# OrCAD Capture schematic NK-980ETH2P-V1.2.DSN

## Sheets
1 Block Diagram: size A; title: NK-980ETH2P; rev: 1.2; company: nuvoTon Technology Corp.; note: Block Diagram
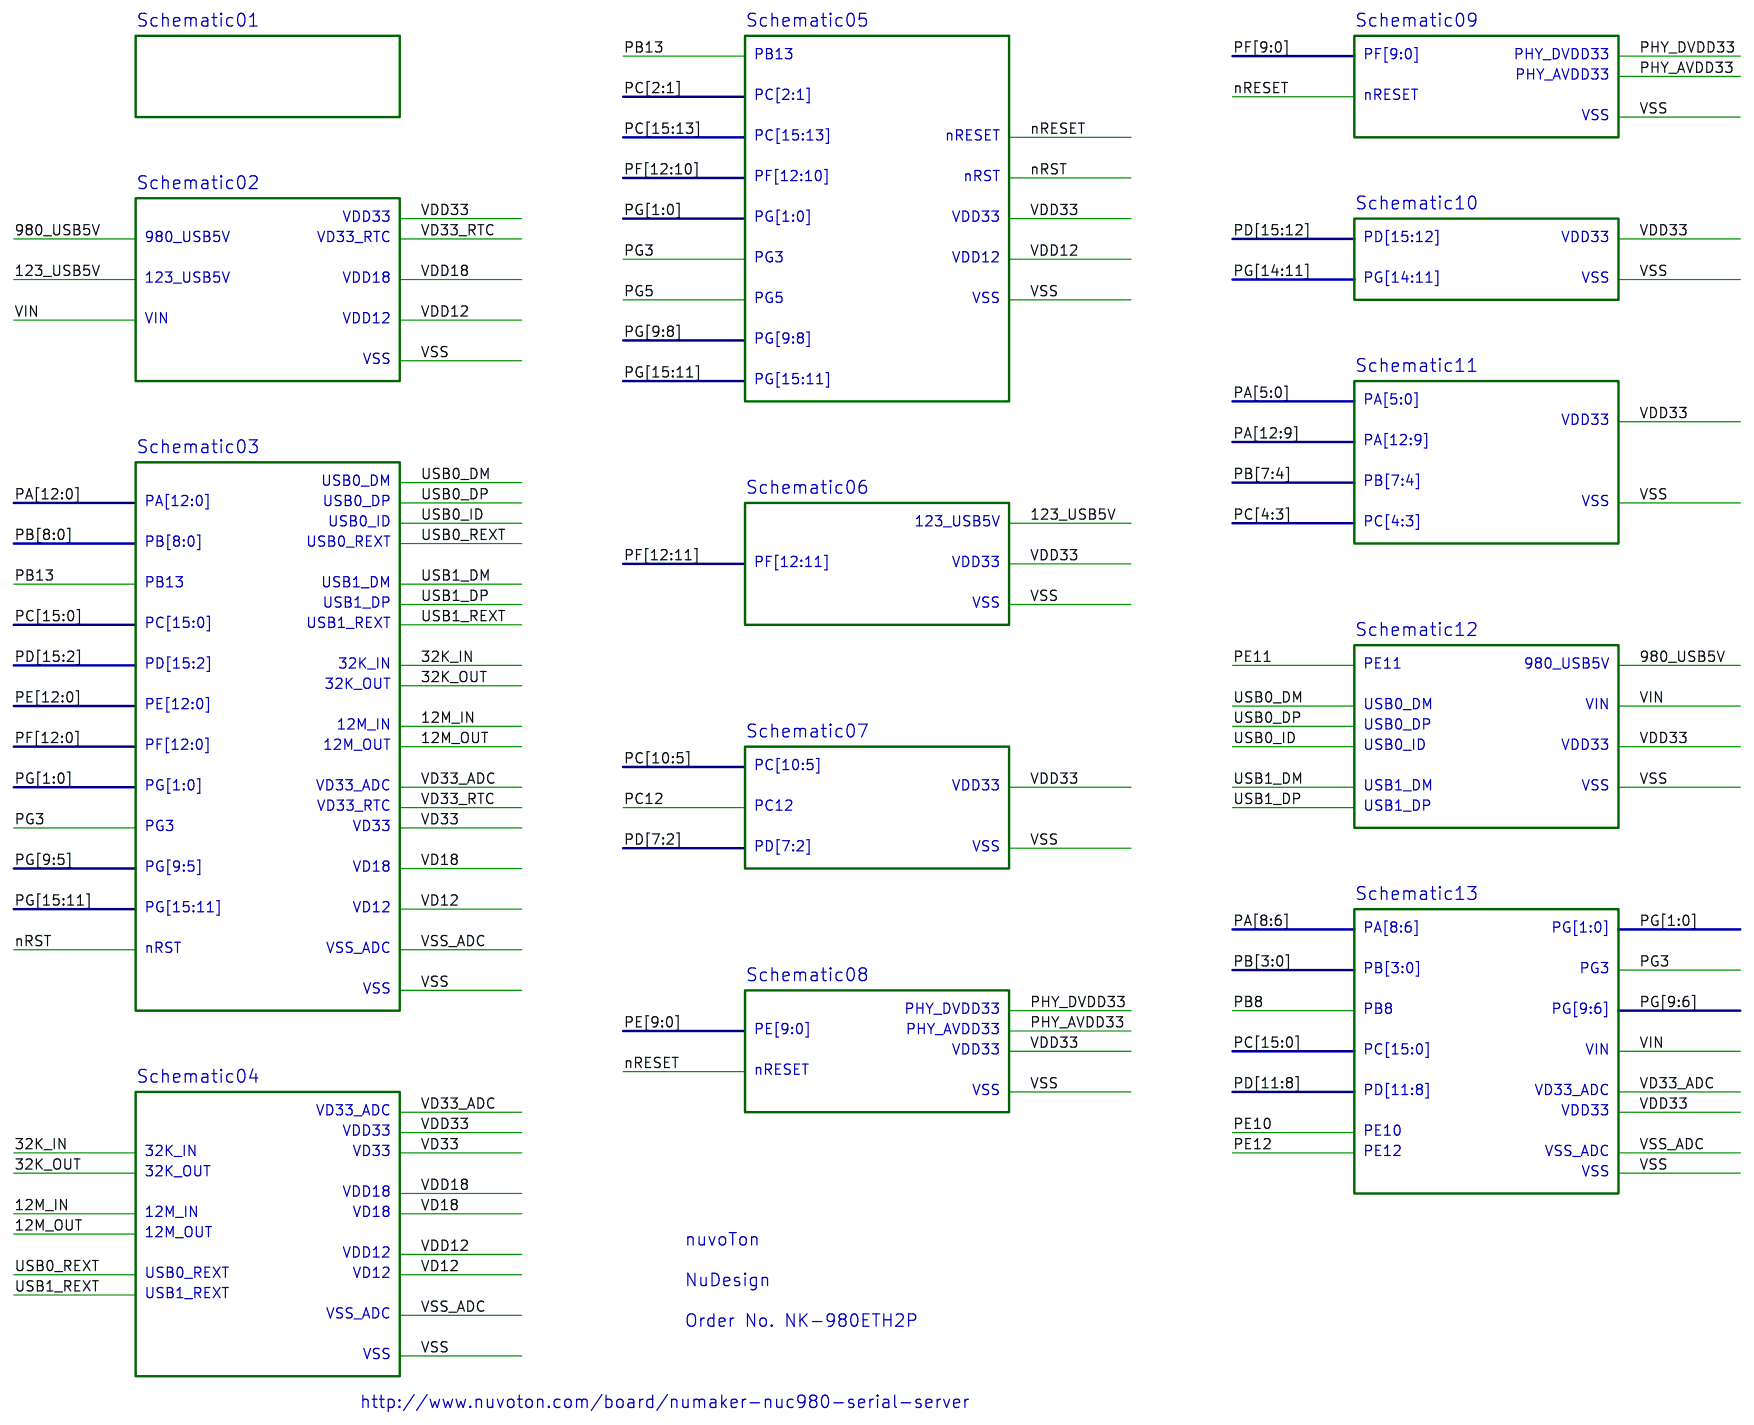
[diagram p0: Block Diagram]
2 Memory: size A; note: Memory; block Schematic07
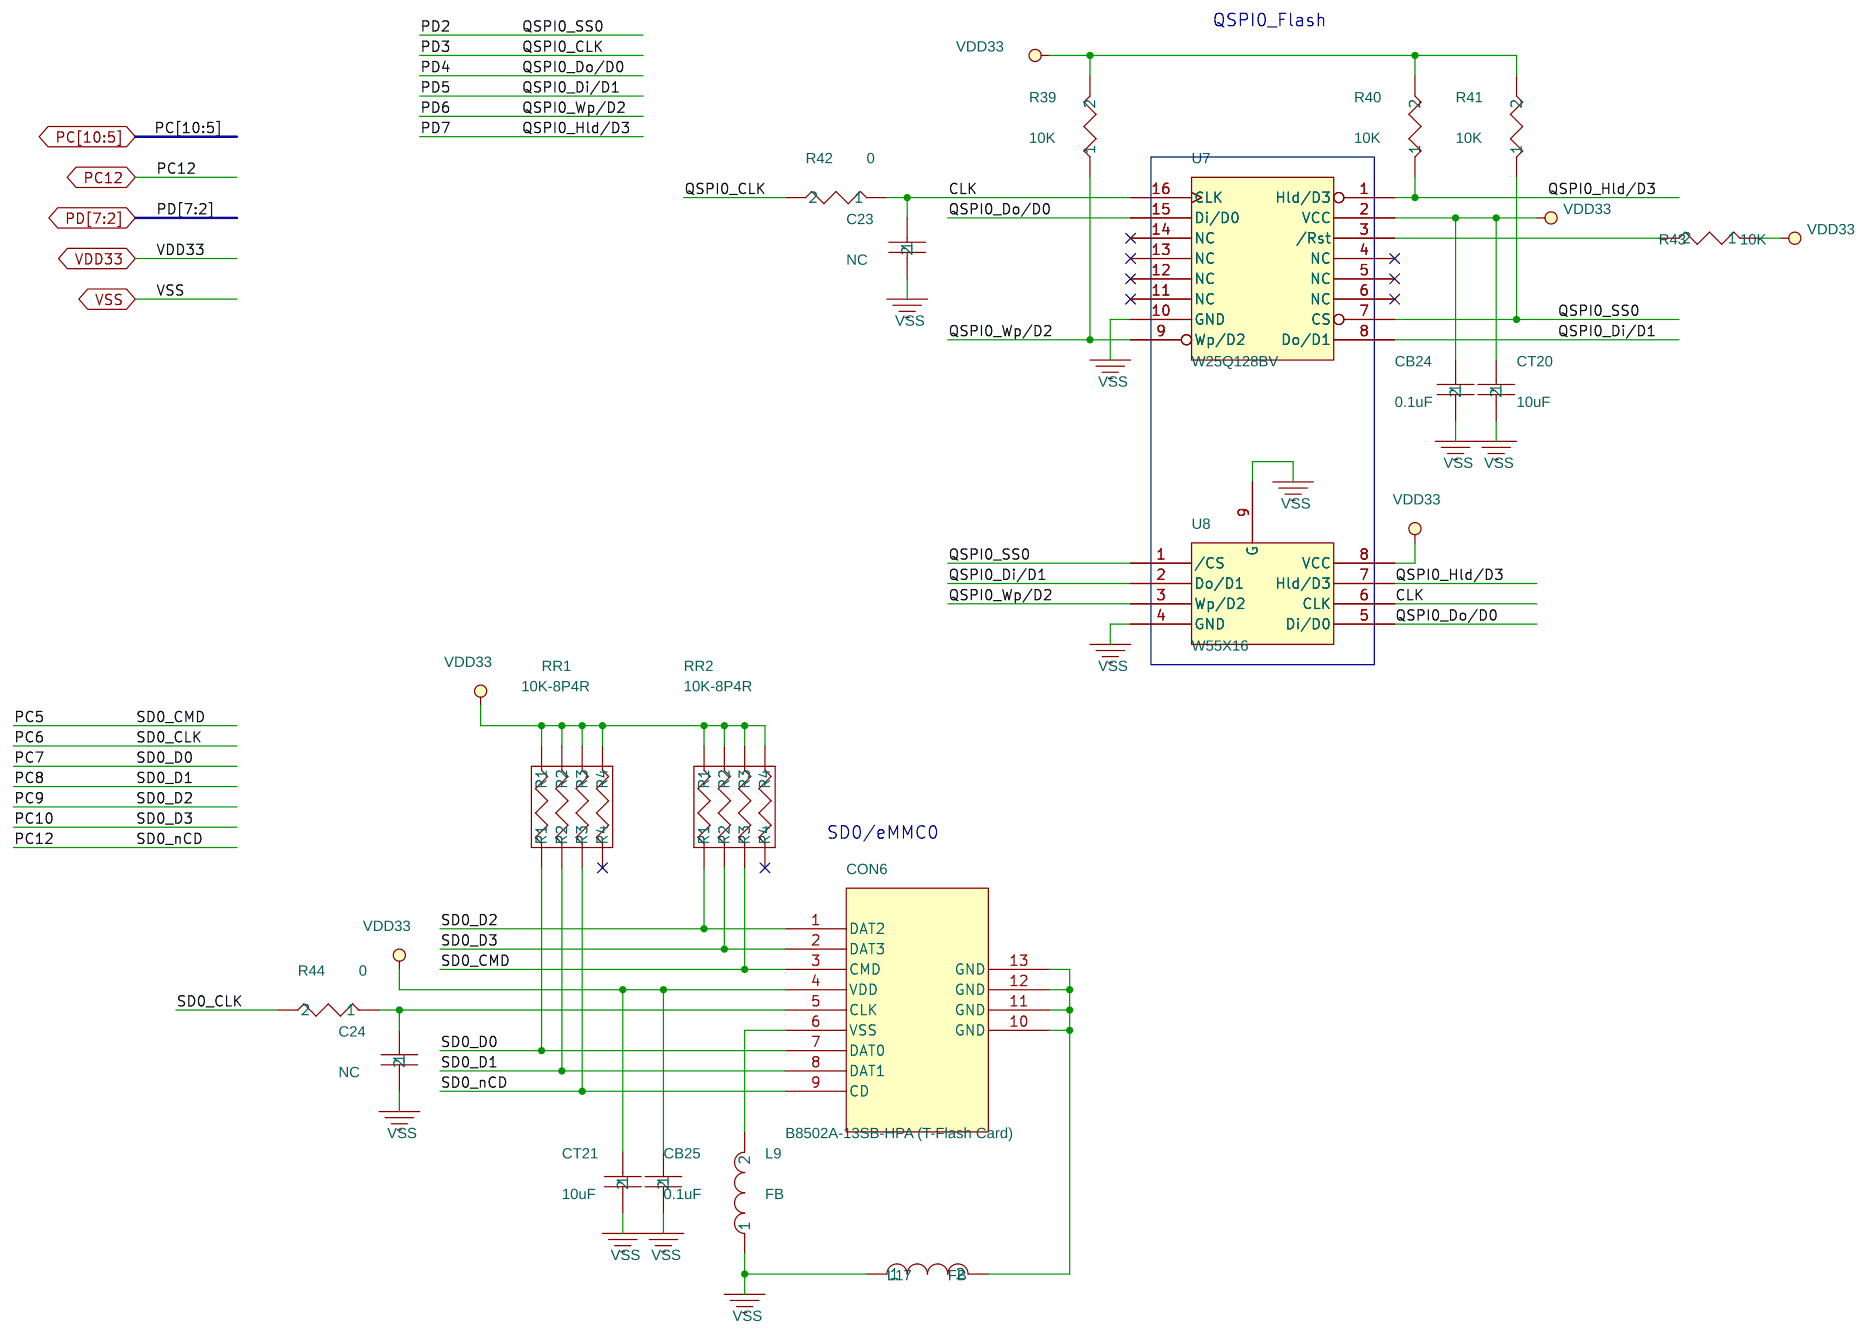
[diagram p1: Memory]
3 RMII_PE: size A; note: RMII_PE; block Schematic08
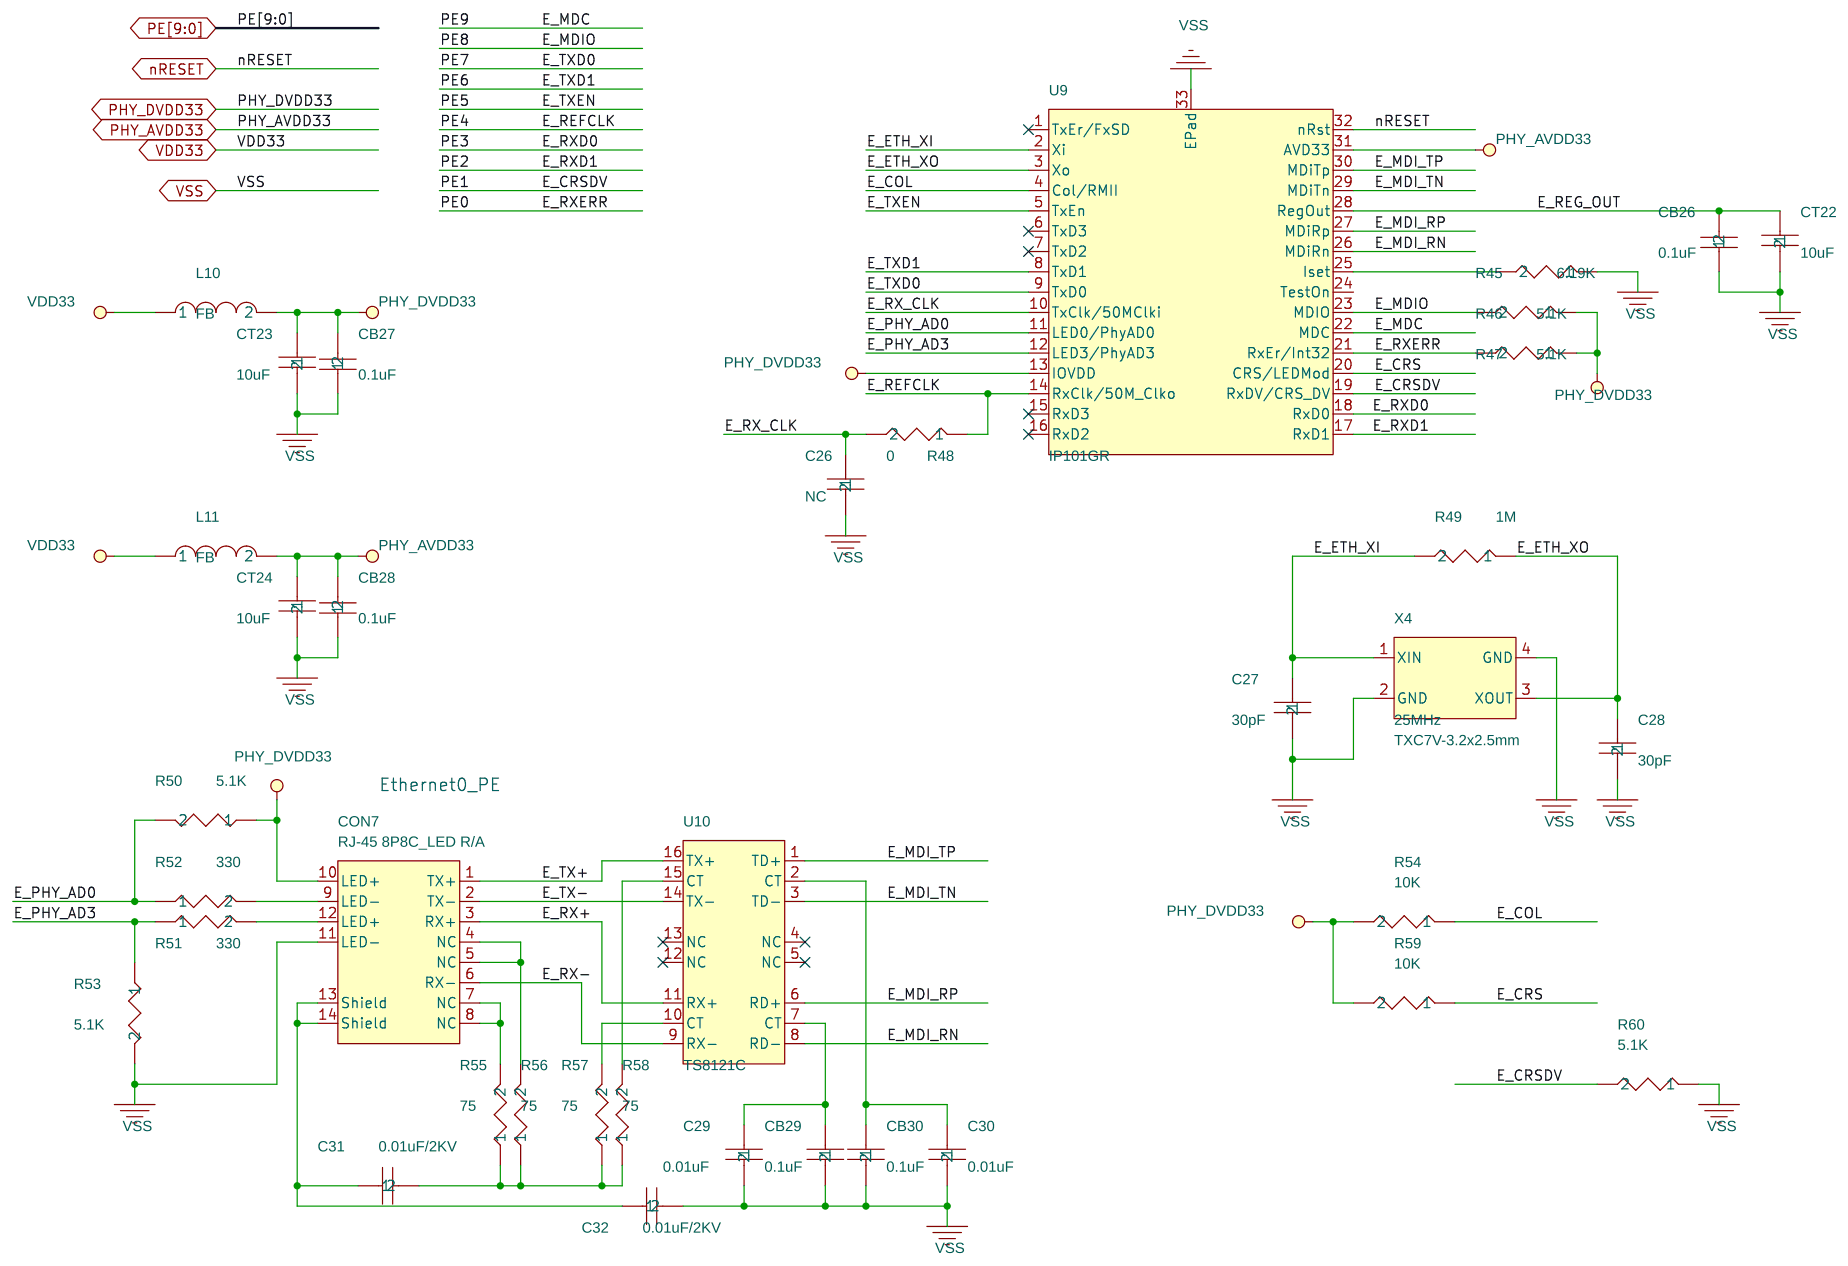
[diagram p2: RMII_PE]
4 Power Filter: size A; note: Power Filter; block Schematic04
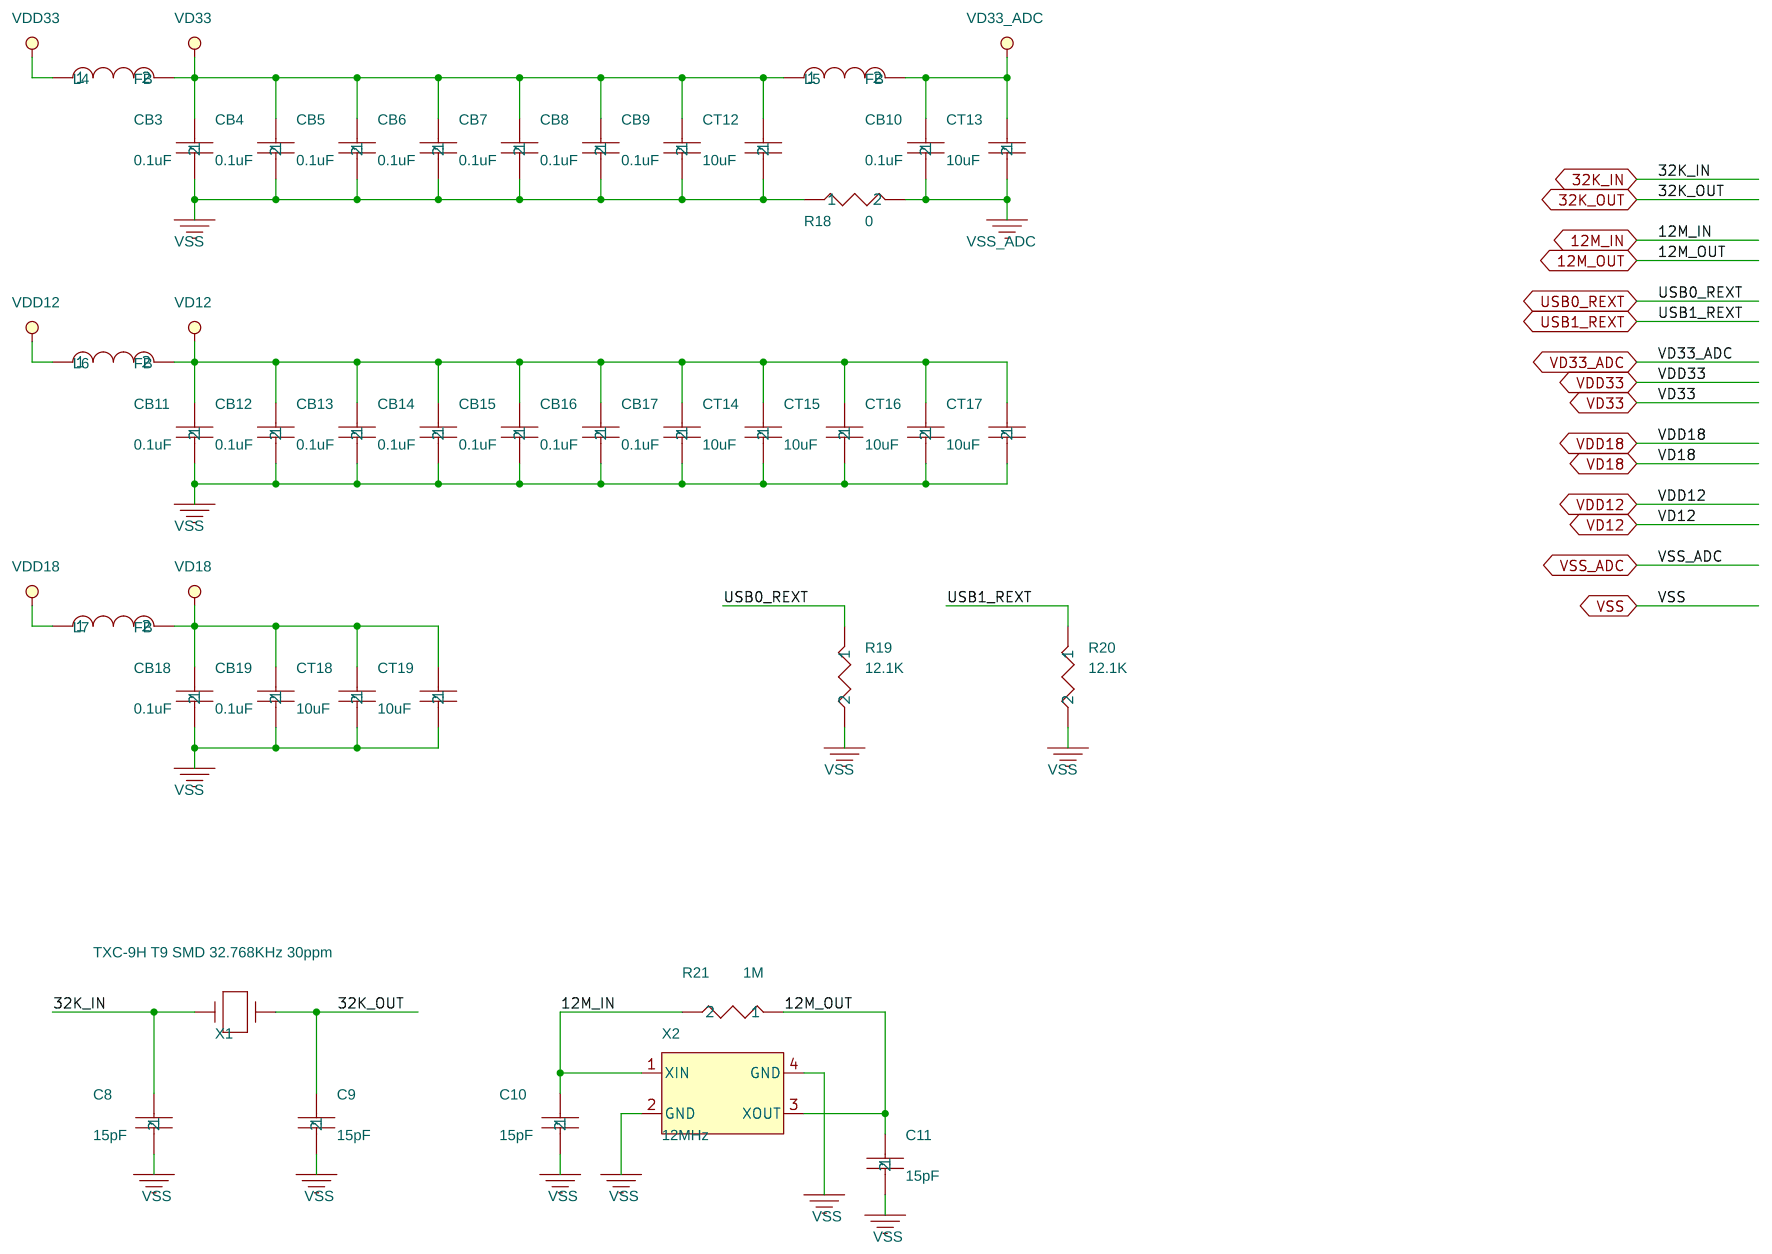
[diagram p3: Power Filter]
5 RMII_PF: size A; note: RMII_PF; block Schematic09
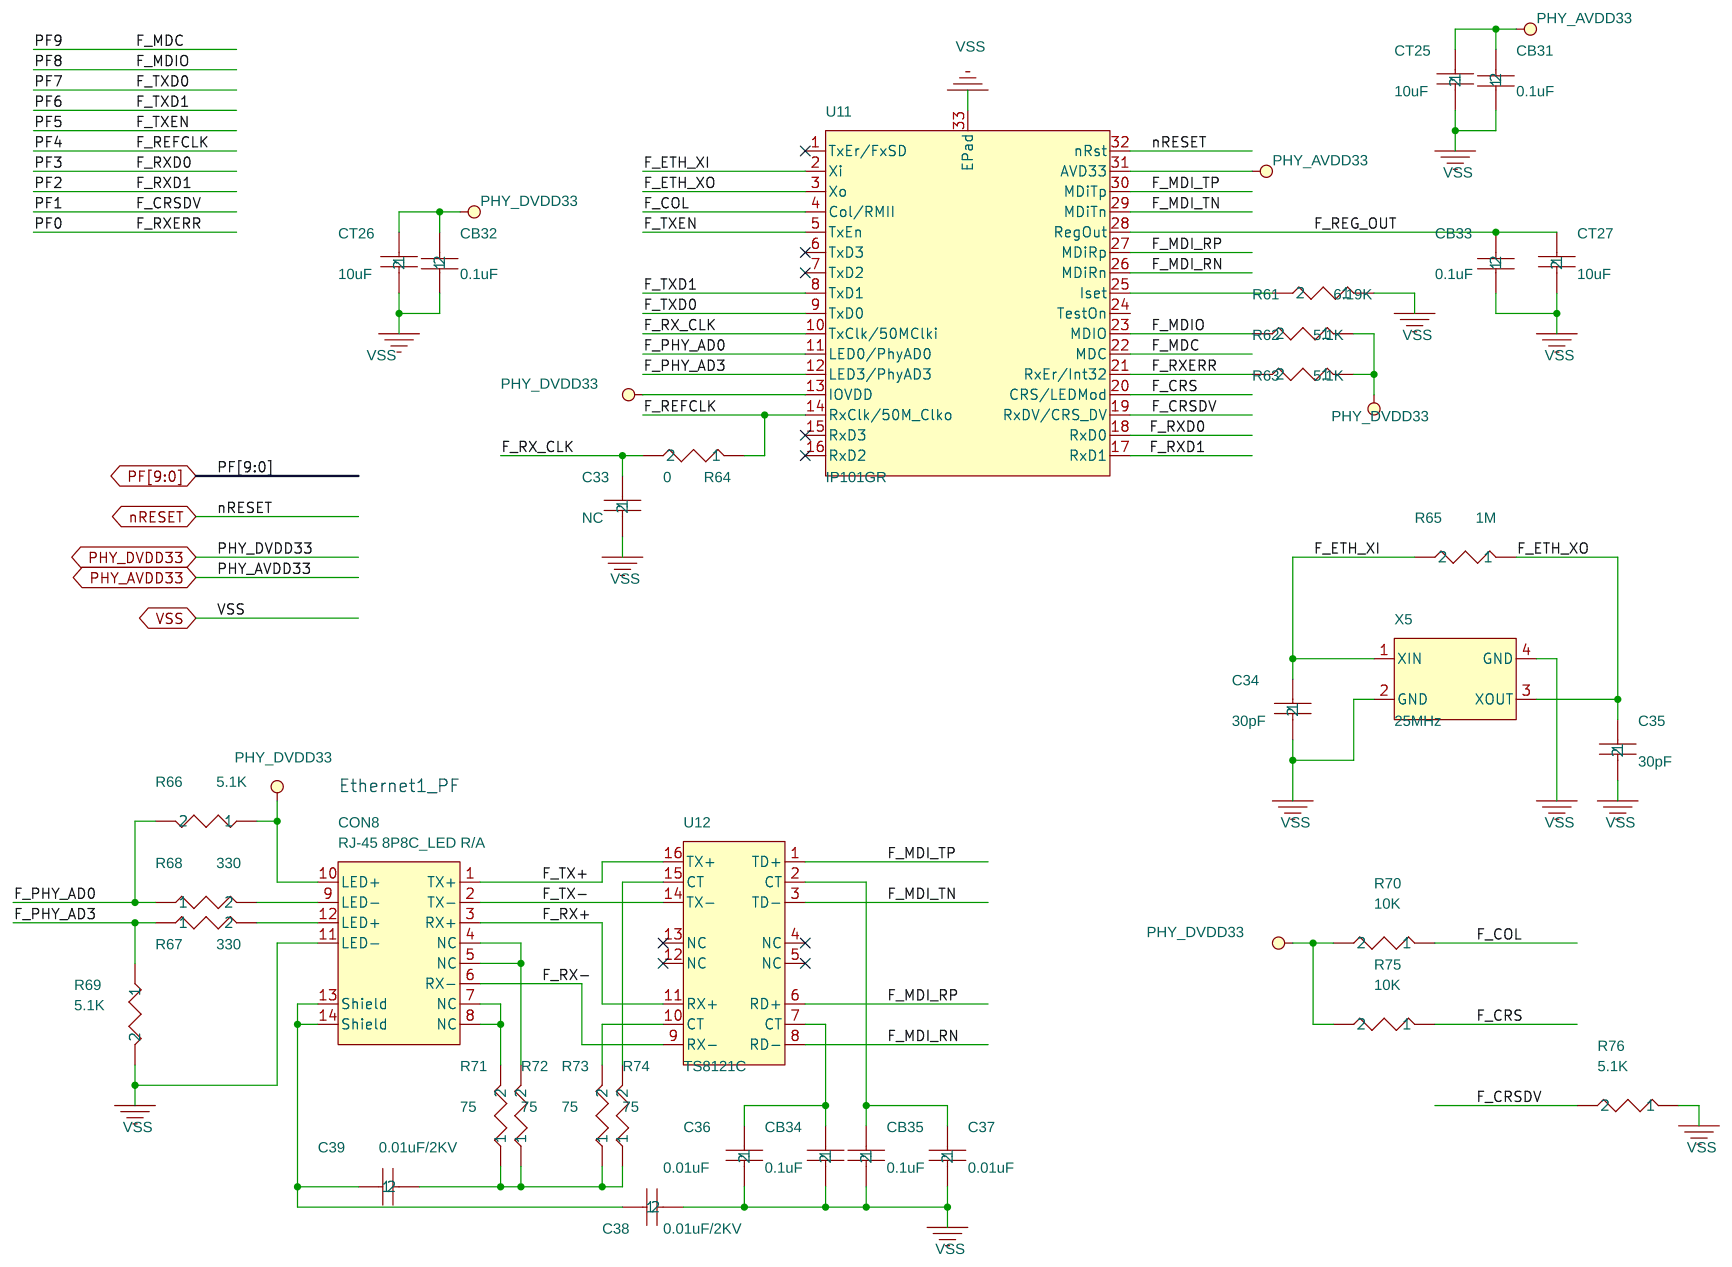
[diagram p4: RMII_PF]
6 UART_A: size A; note: UART_A; block Schematic10
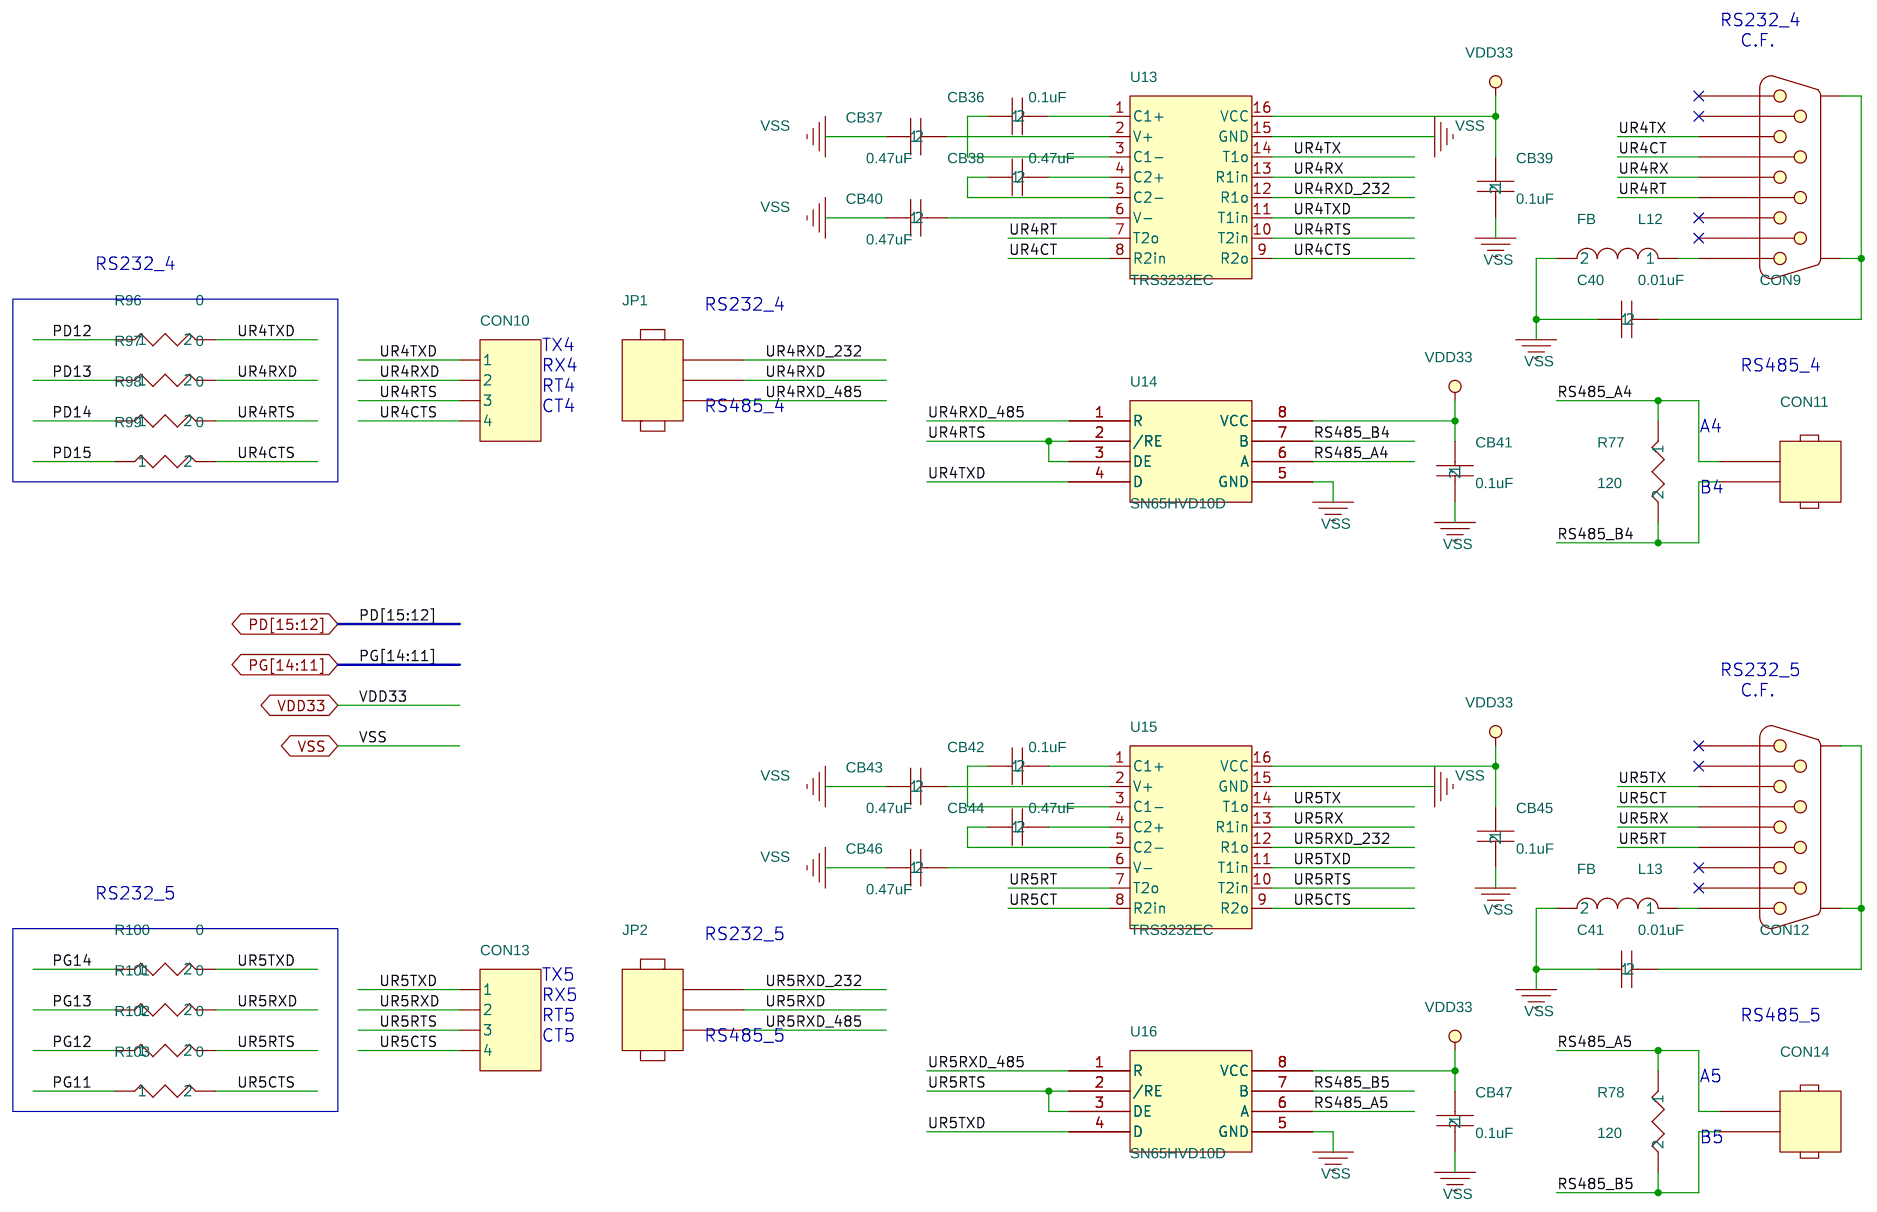
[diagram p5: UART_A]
7 GPIO List: note: GPIO List
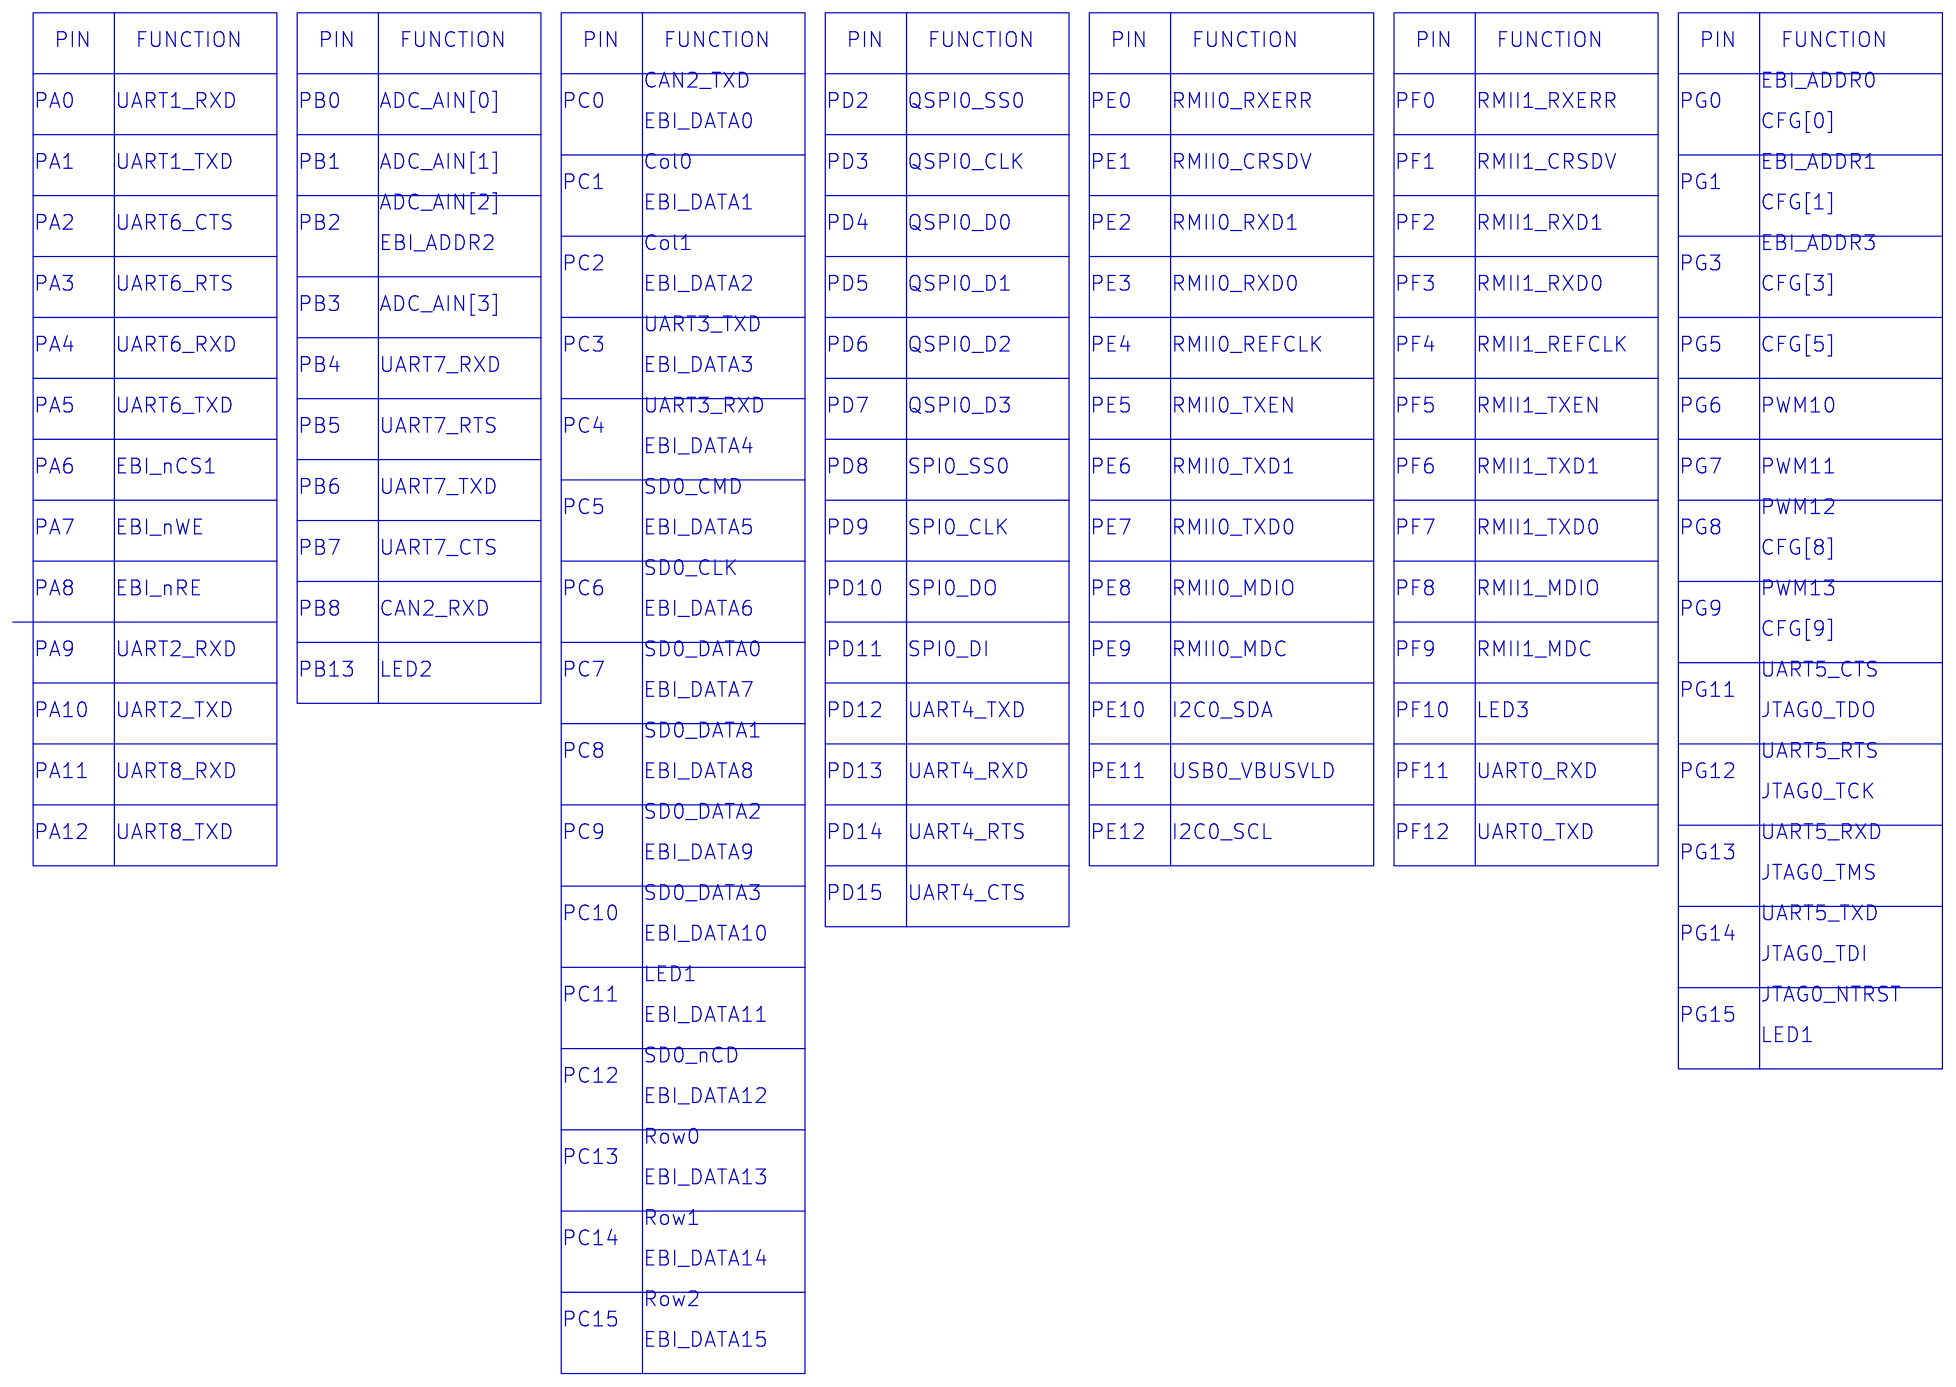
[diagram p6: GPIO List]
8 Power: size A; note: Power; block Schematic02
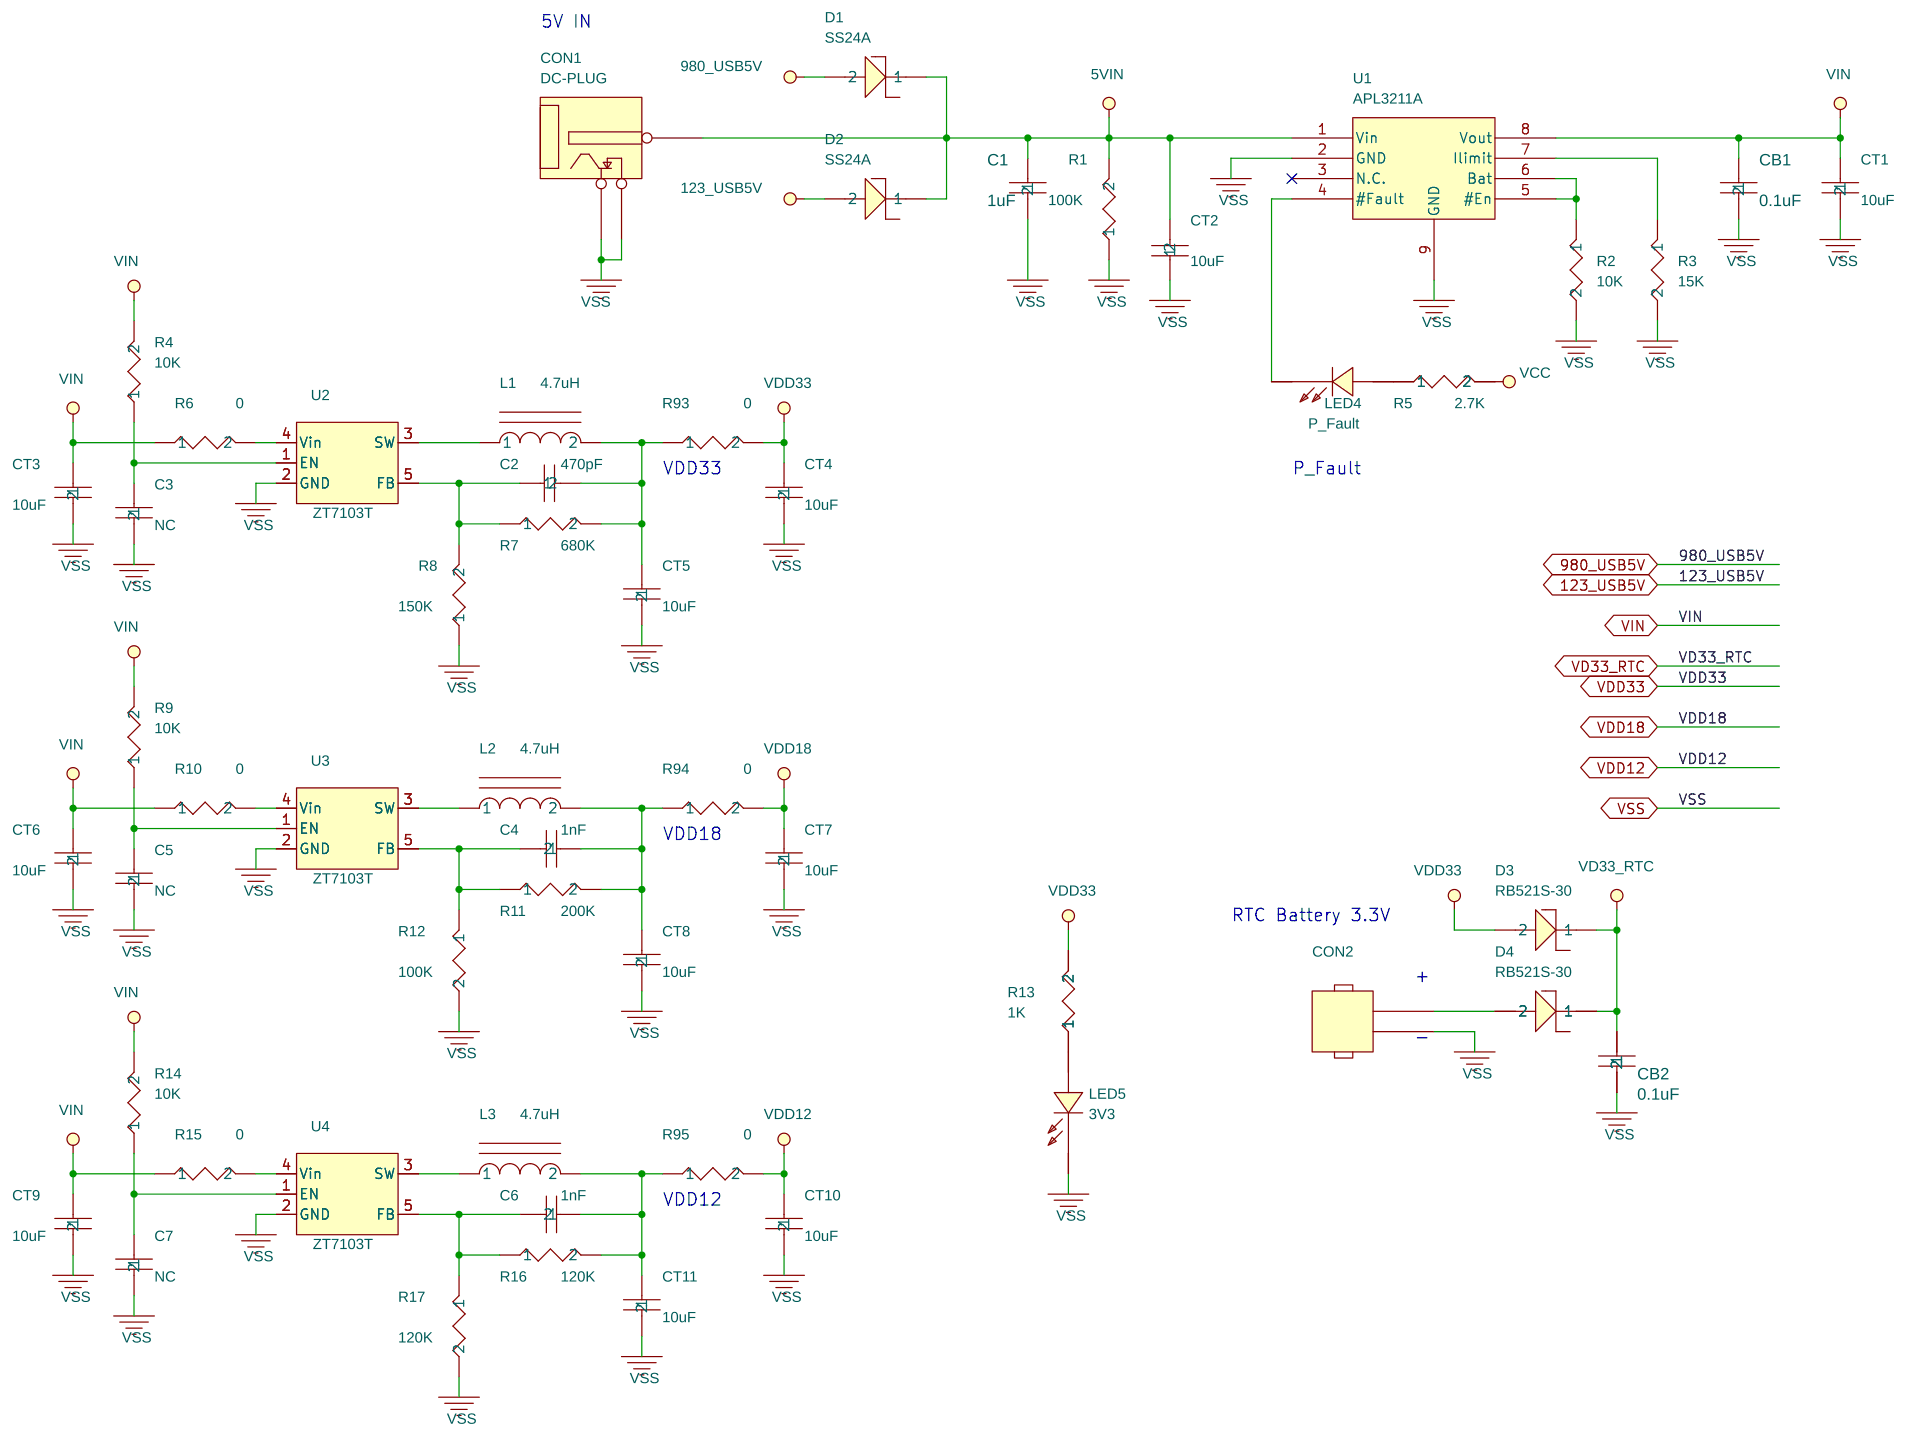
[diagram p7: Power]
9 UART_B: size A; note: UART_B; block Schematic11
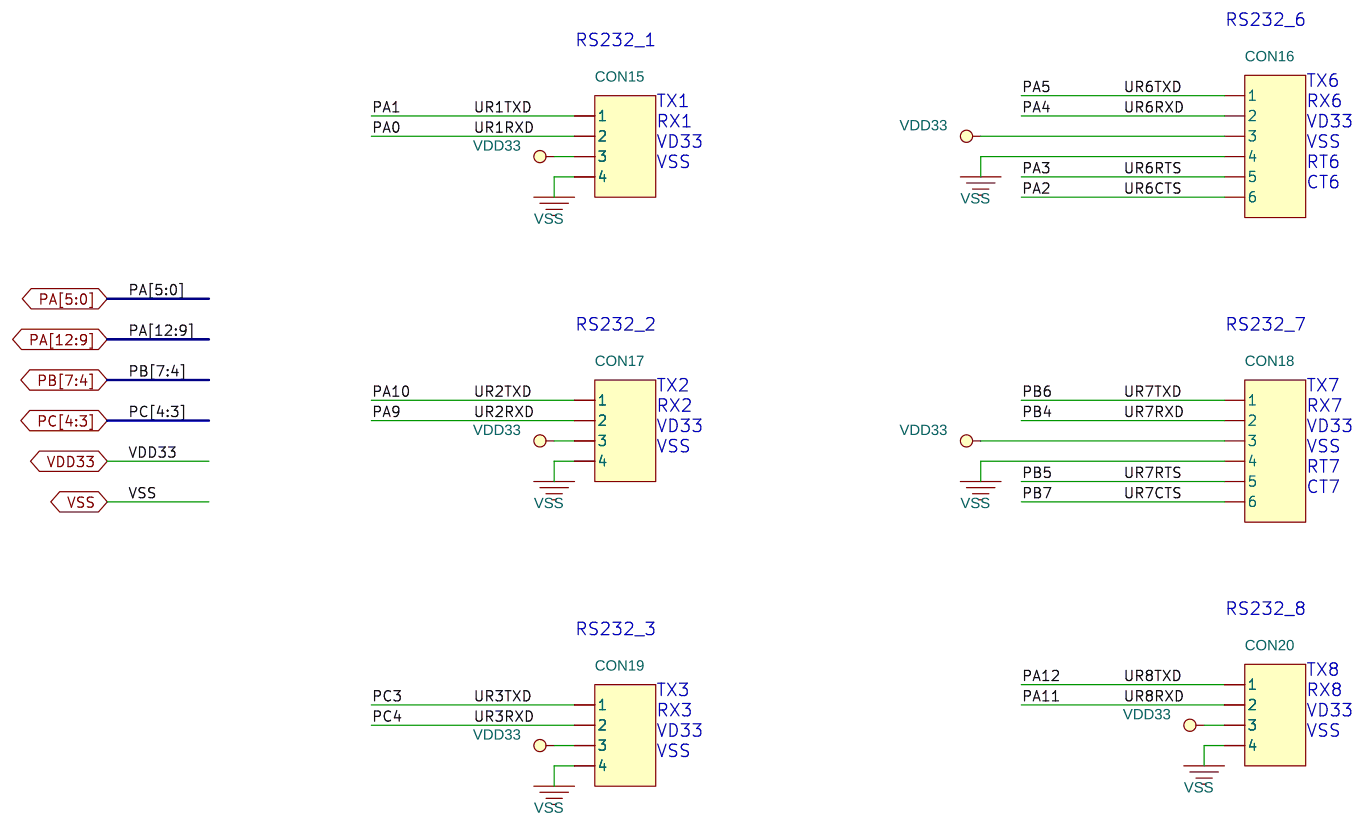
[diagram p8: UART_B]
10 Configure: size Custom; note: Configure; block Schematic05
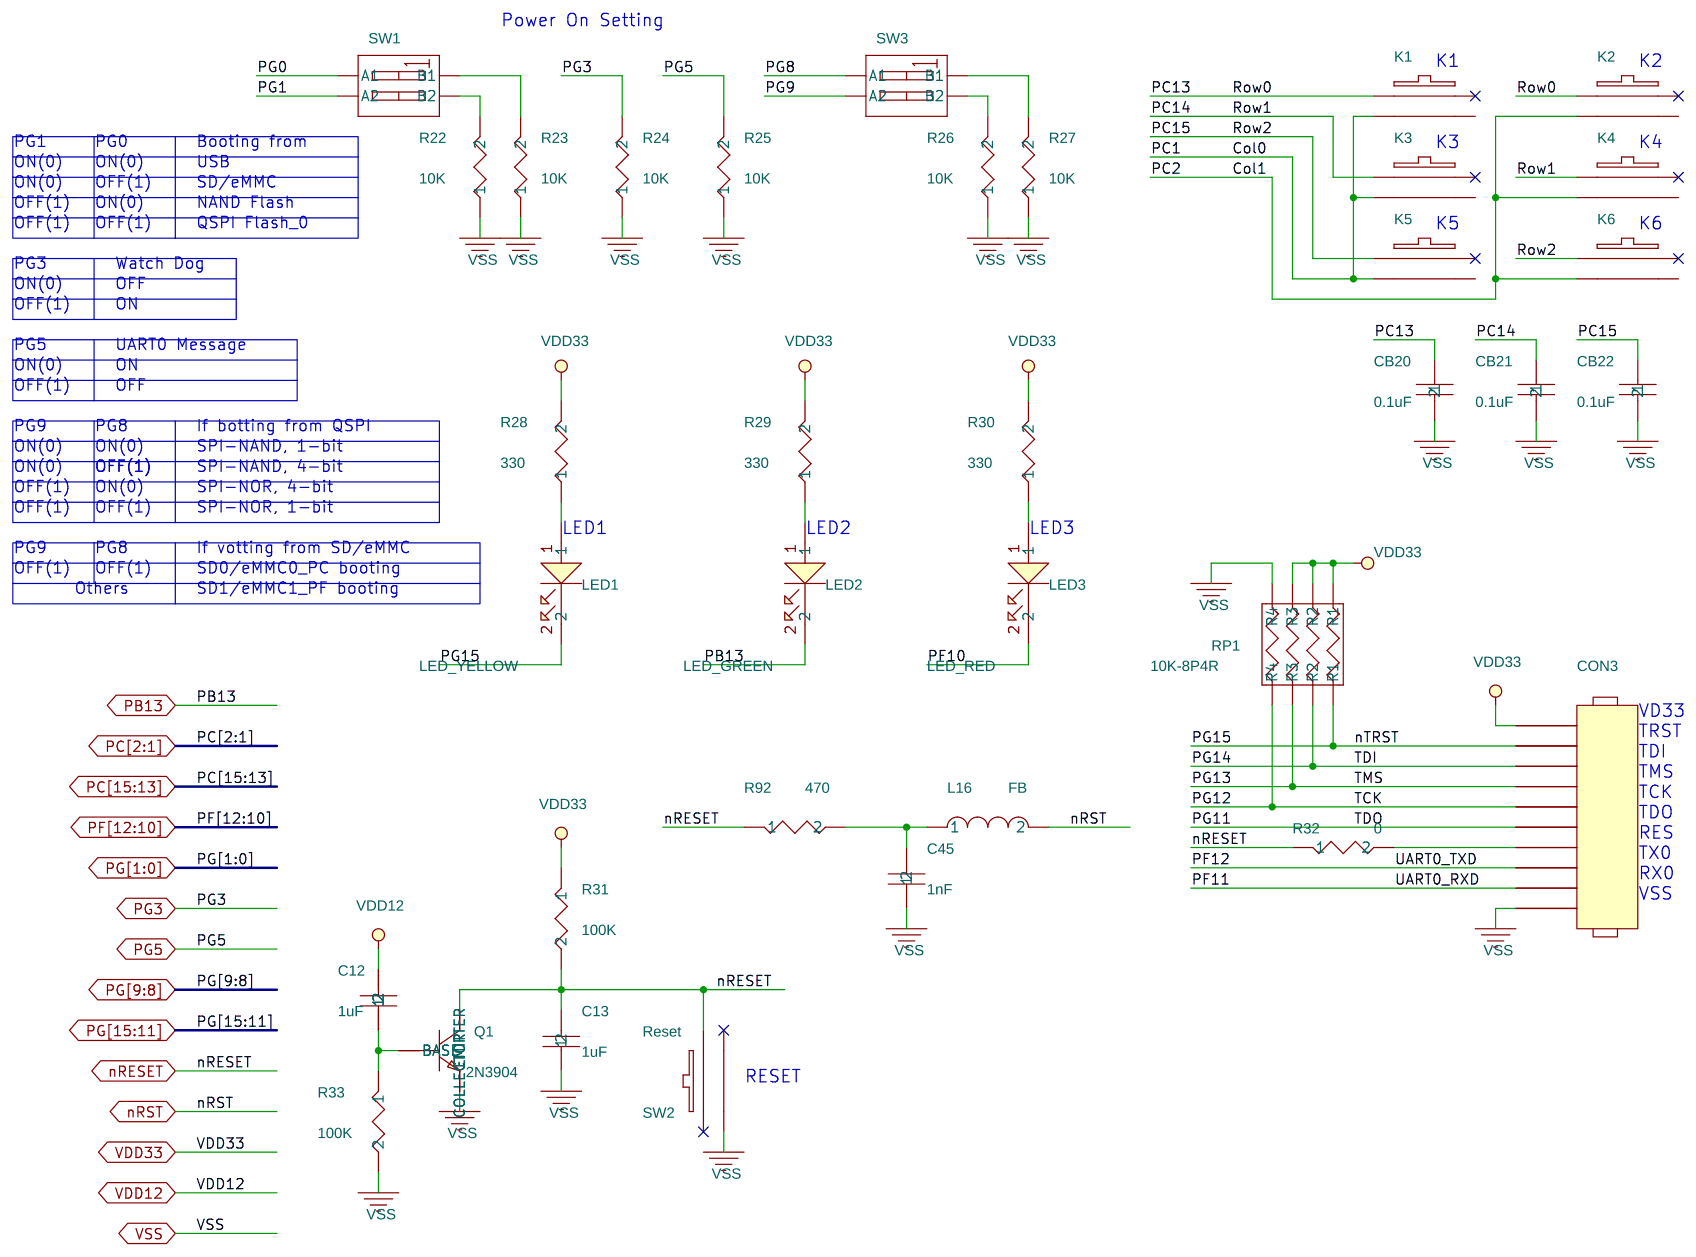
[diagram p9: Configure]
11 USB: size A; note: USB; block Schematic12
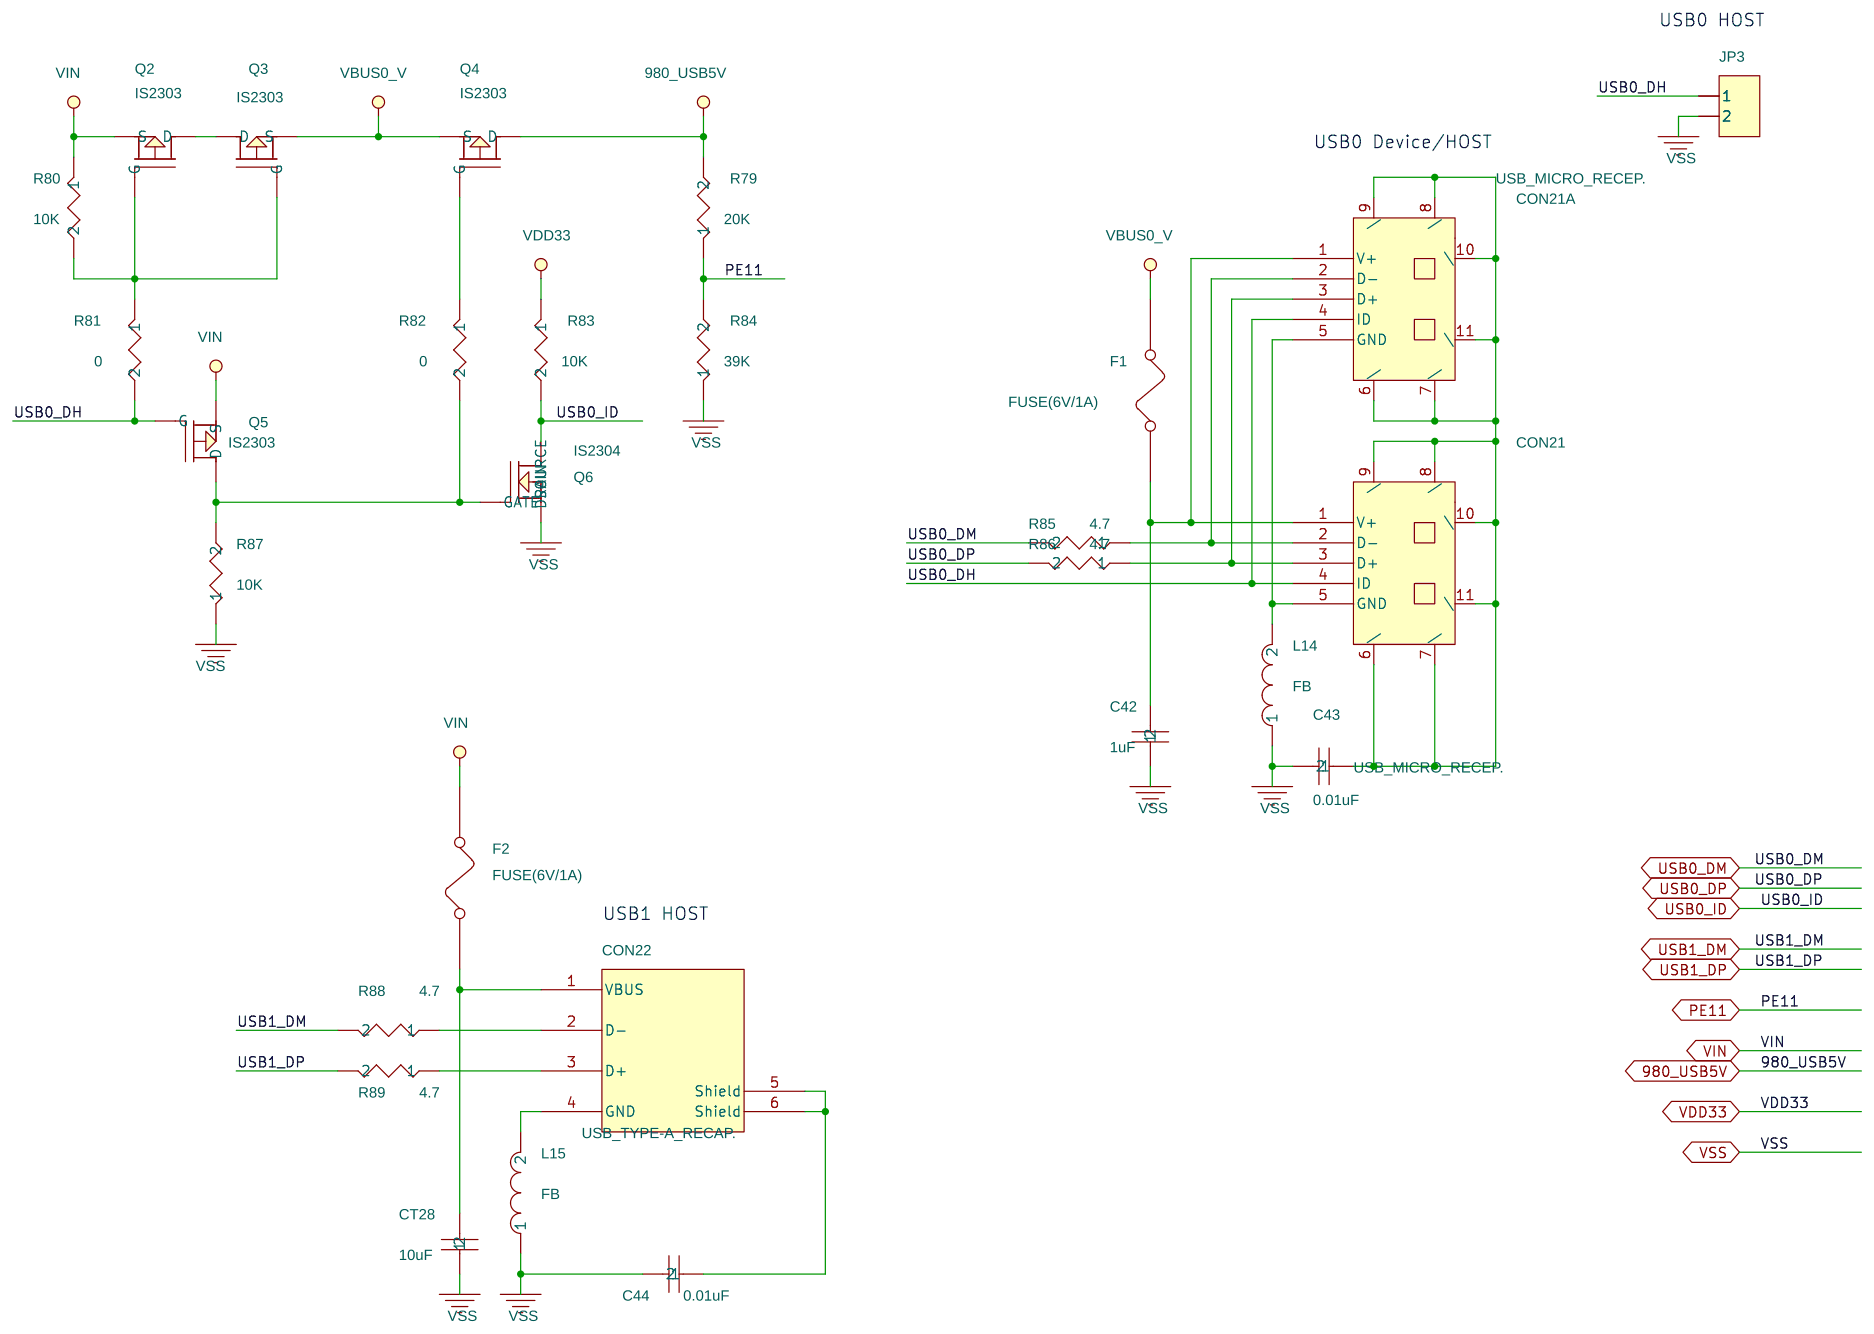
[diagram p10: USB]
12 NUC980DK: size Custom; note: NUC980DK; block Schematic03
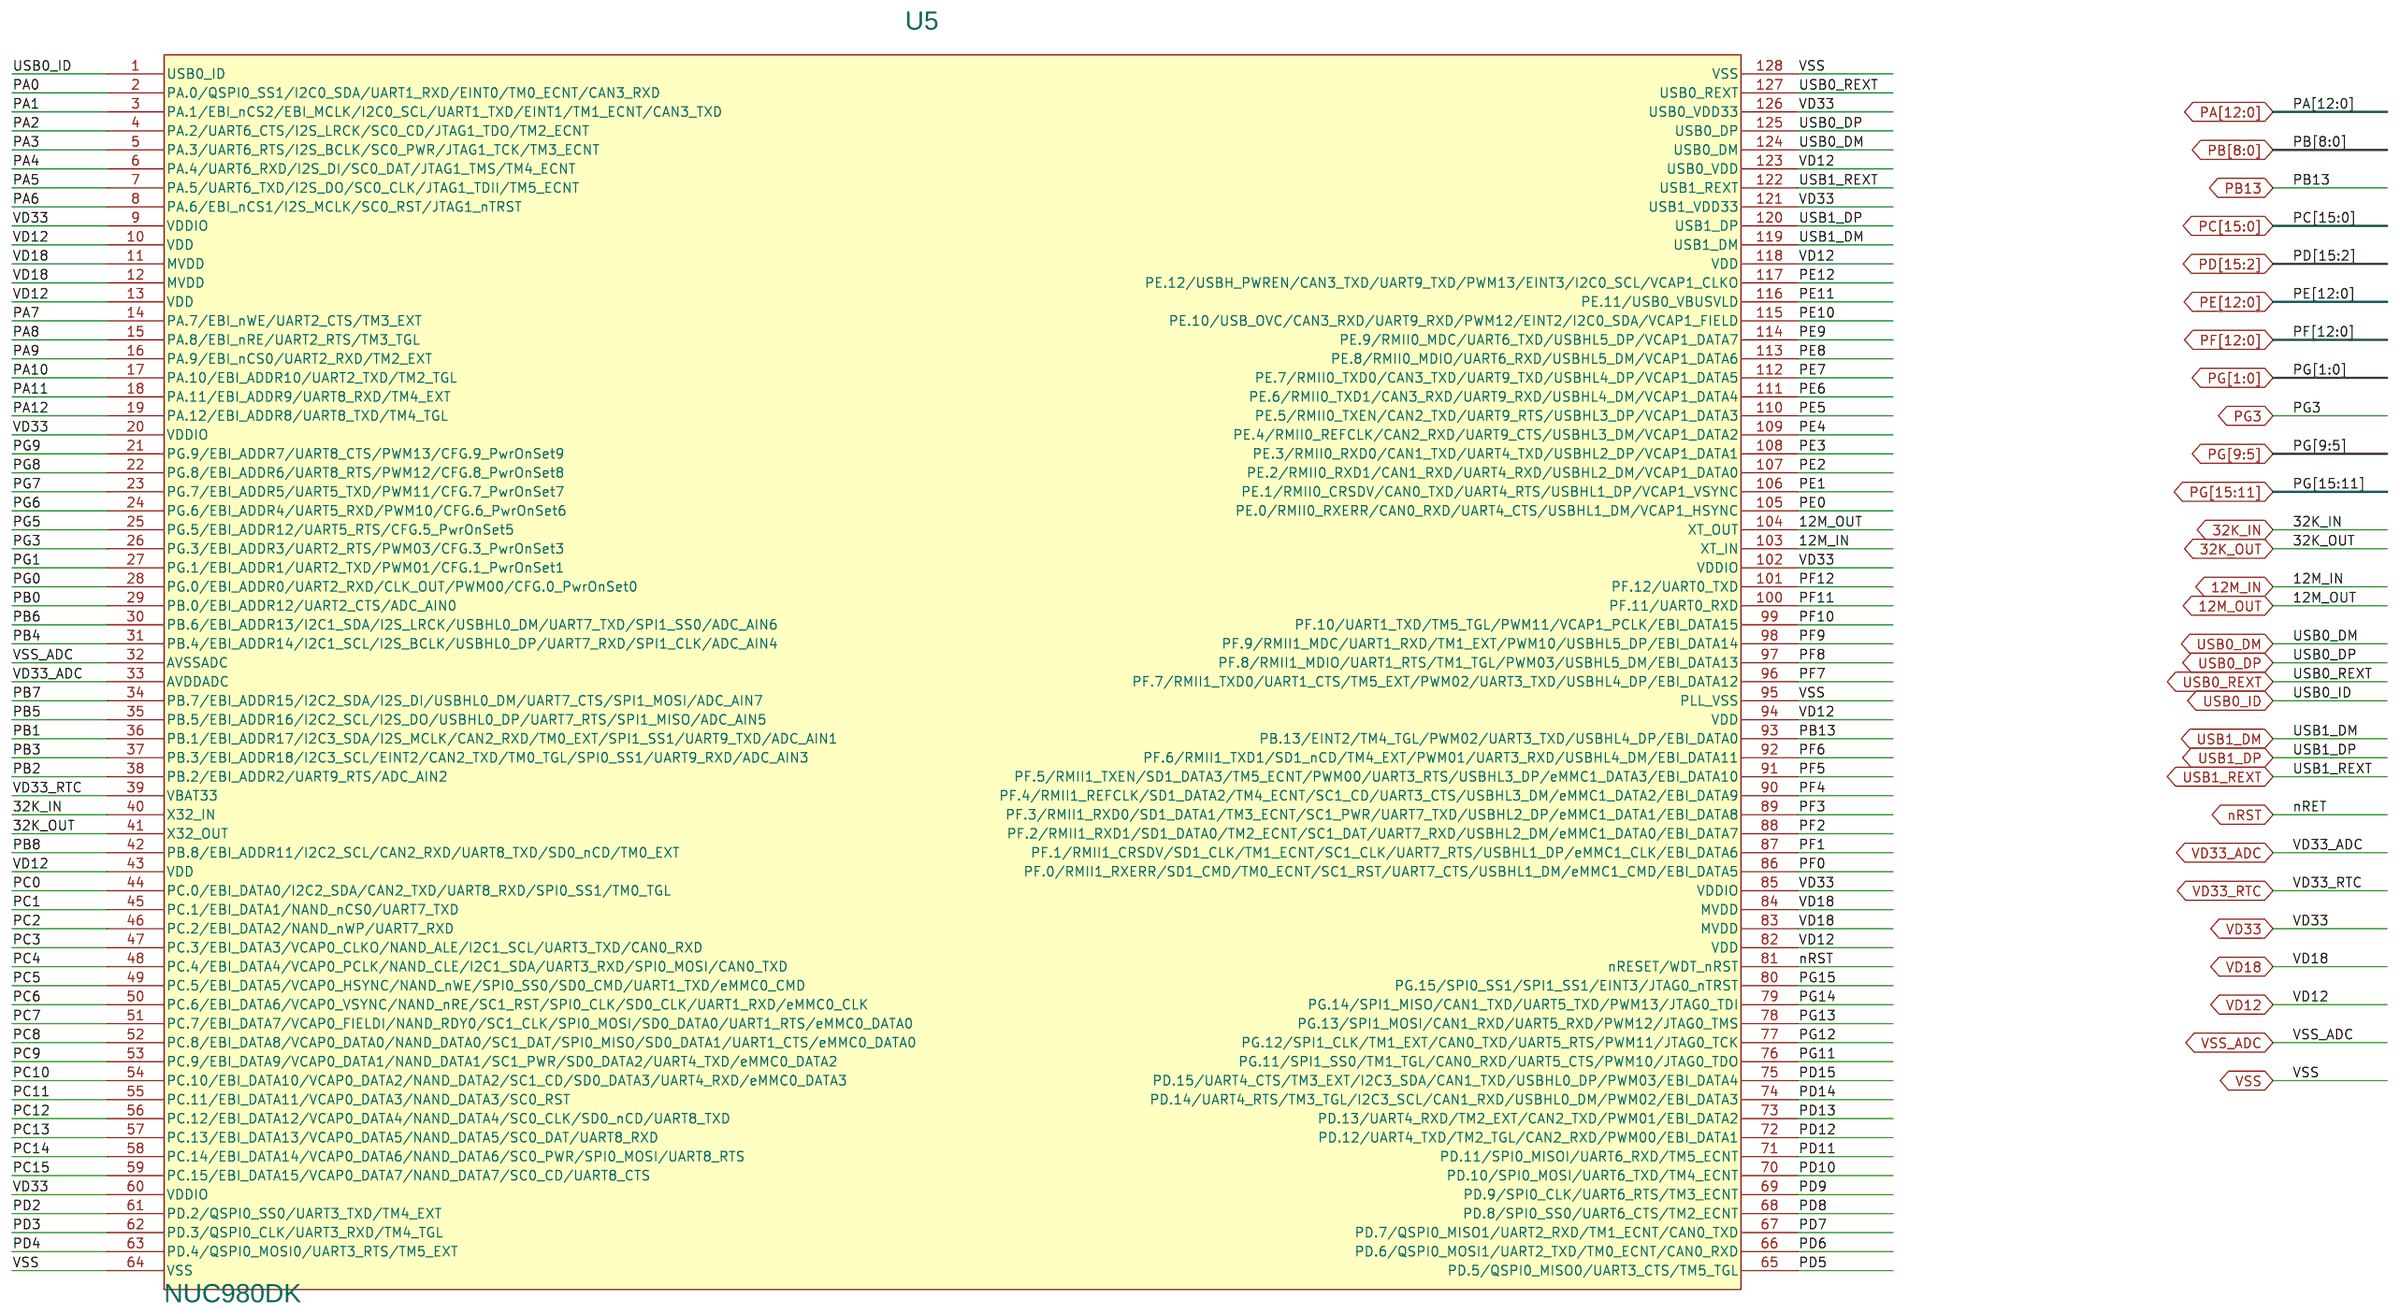
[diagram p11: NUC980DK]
13 NUC123ZD4AN0: size A; note: UNC123ZD4AN0; block Schematic06
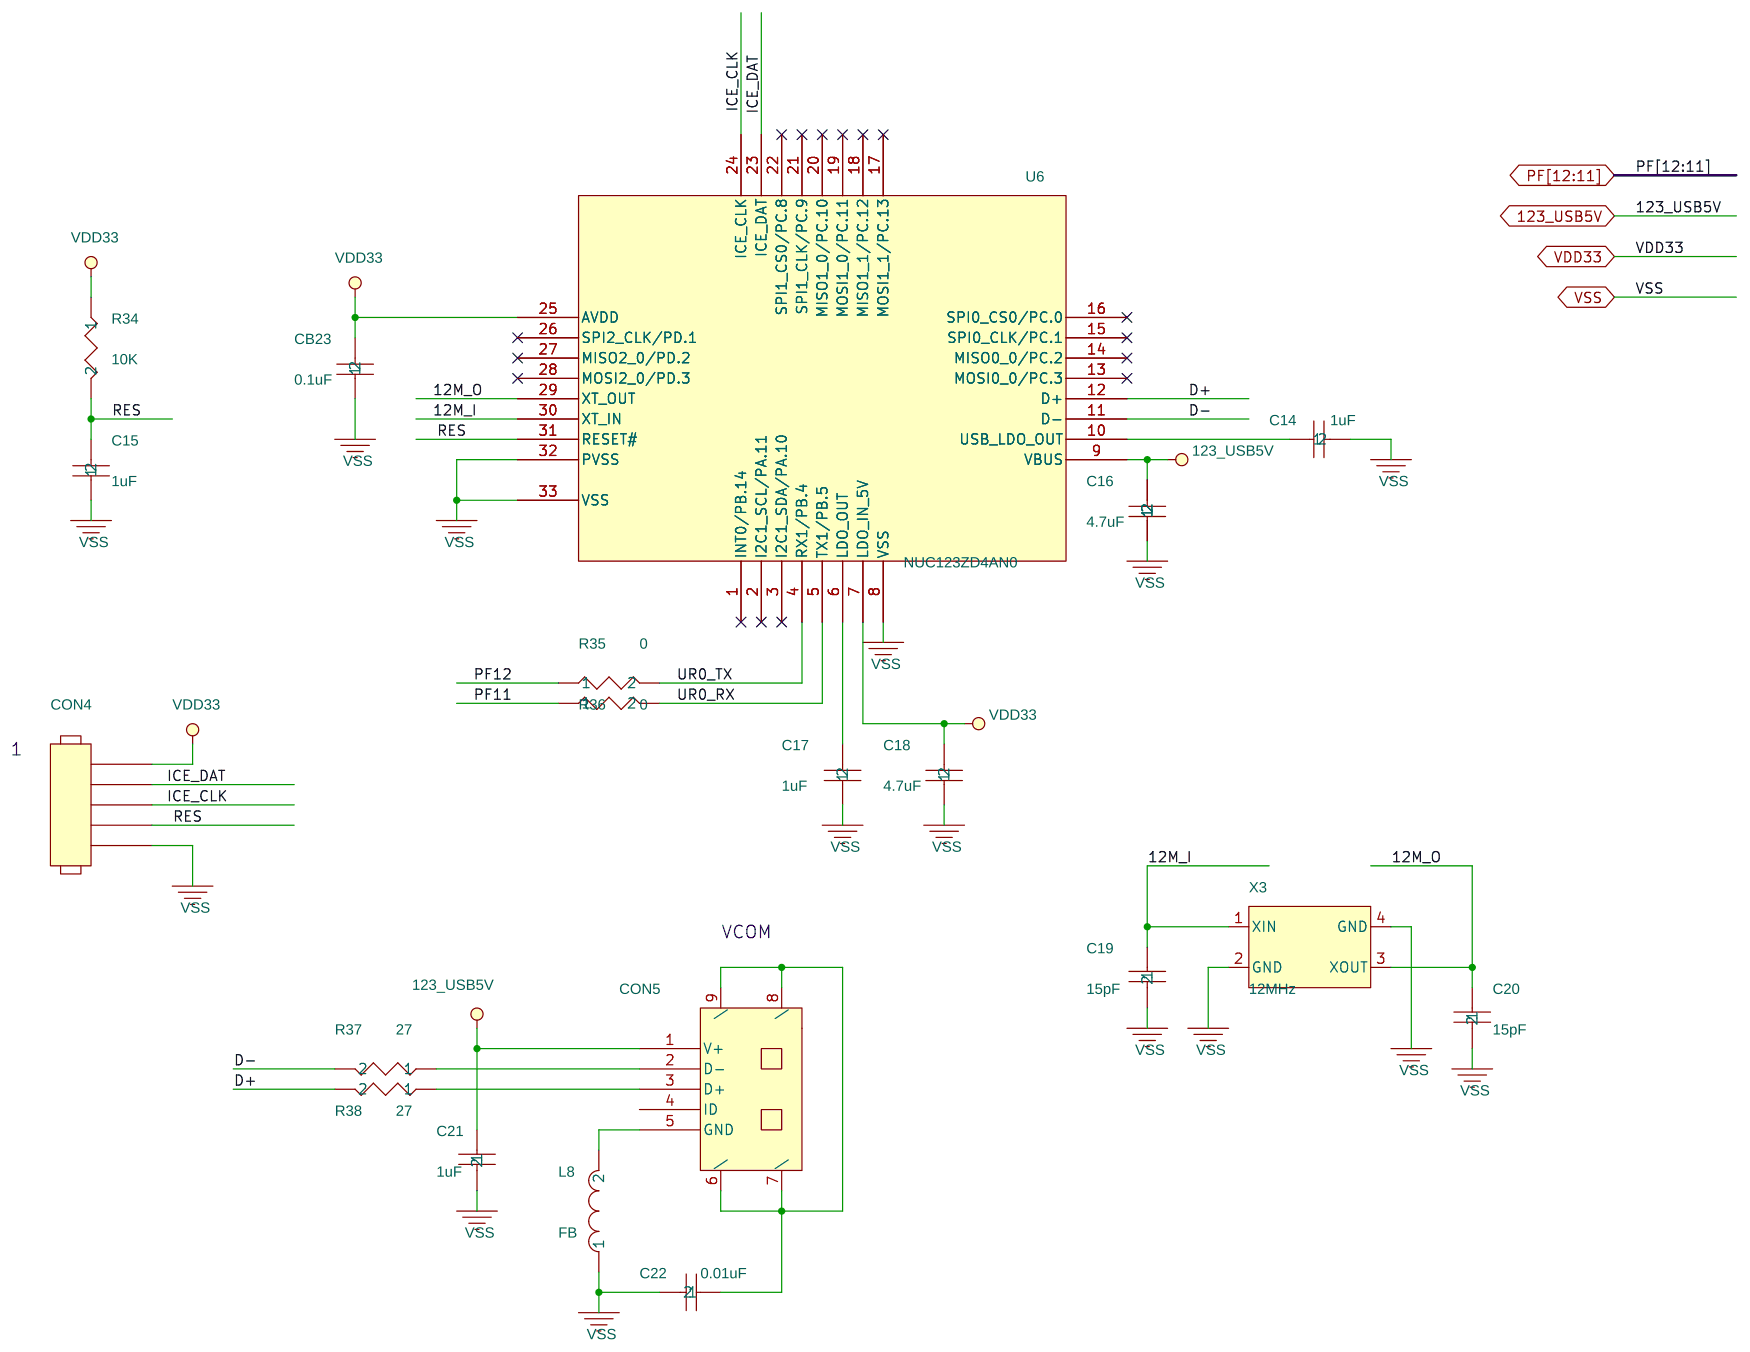
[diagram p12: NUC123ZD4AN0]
14 Expand: size A; note: Expand; block Schematic13
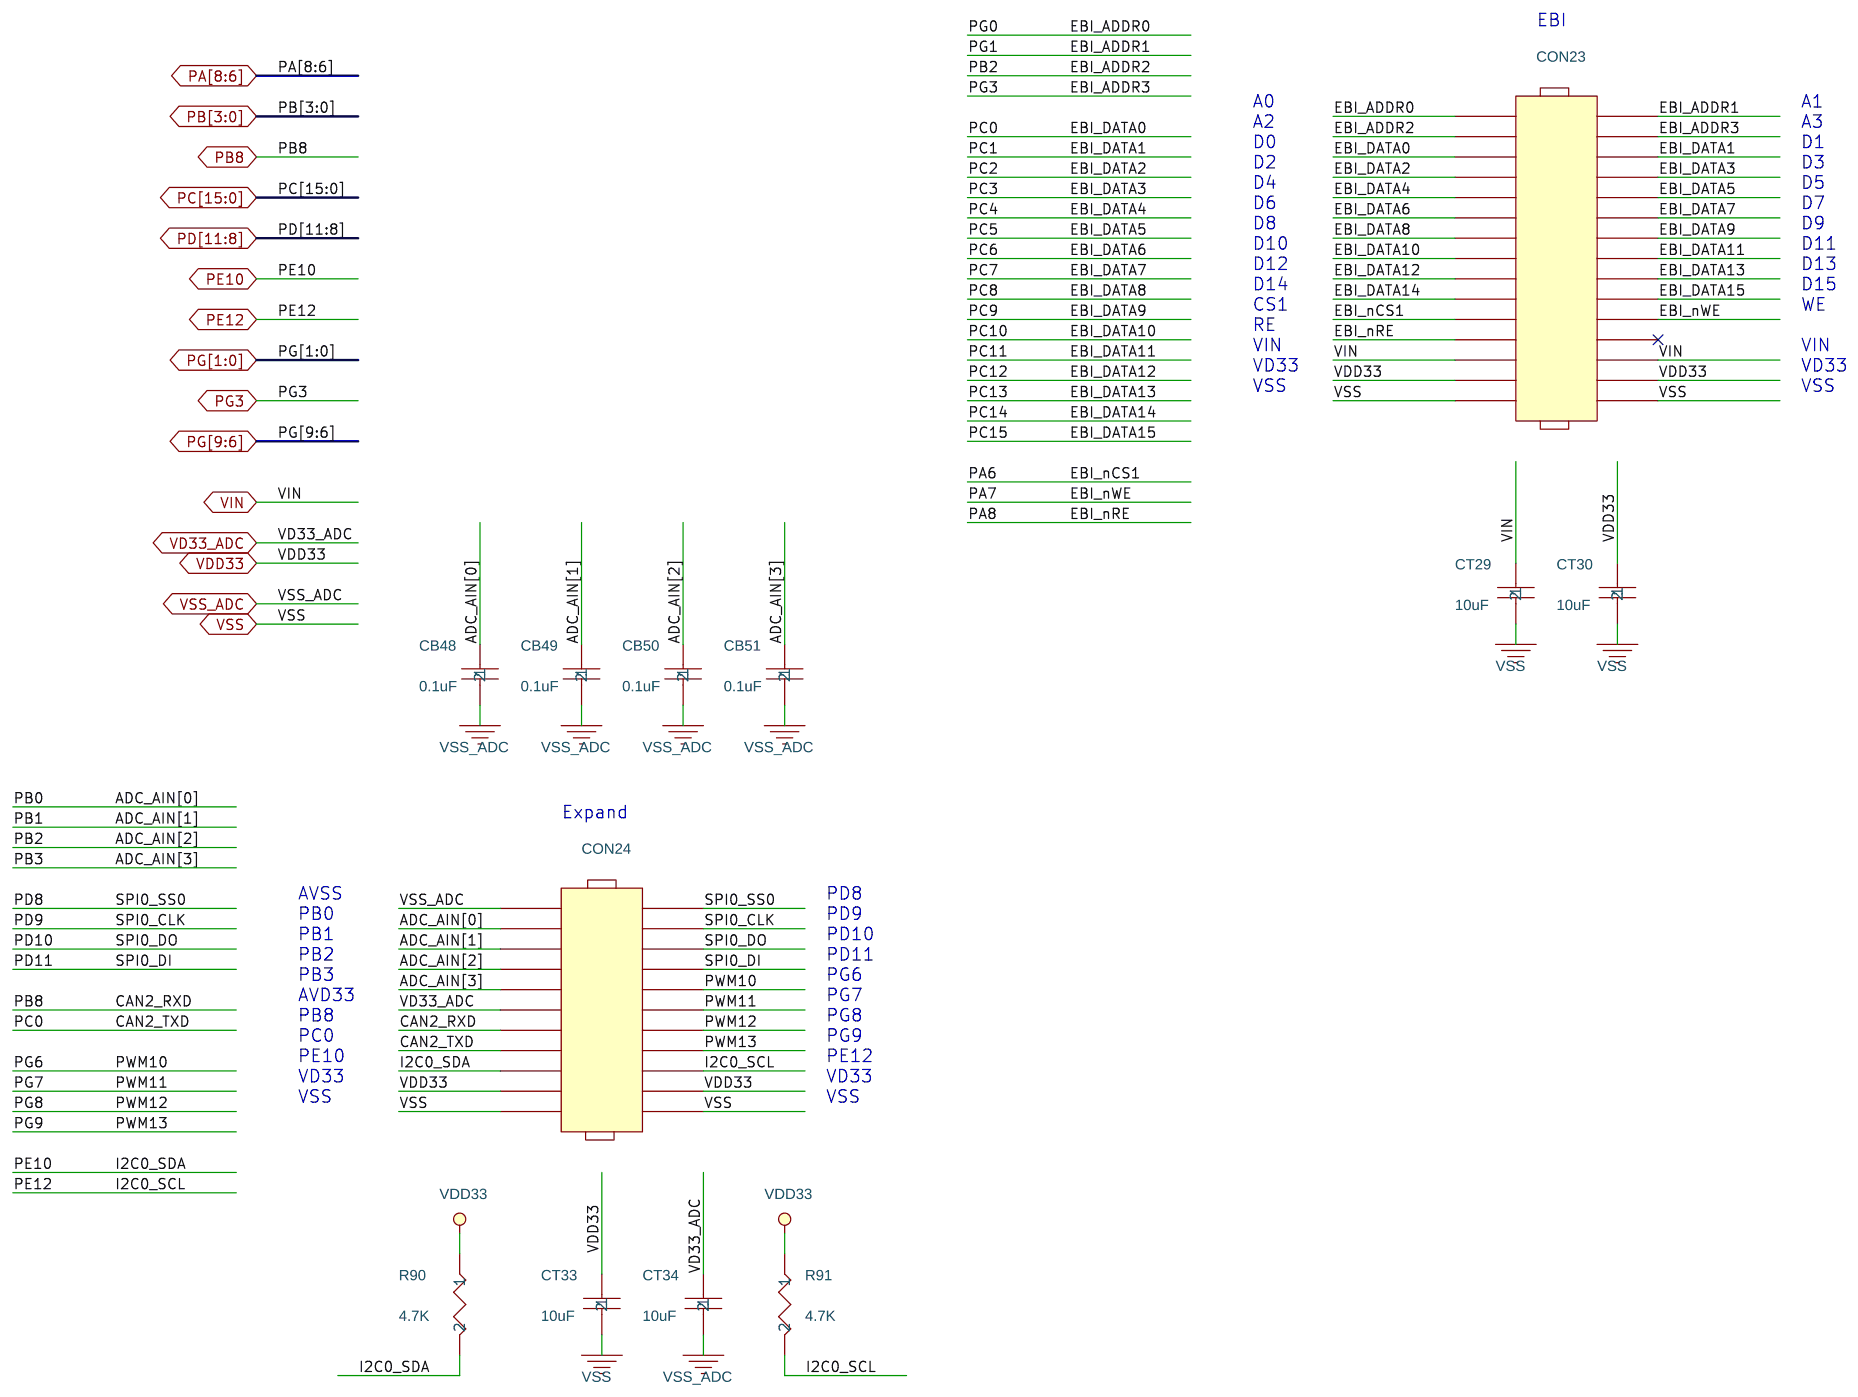
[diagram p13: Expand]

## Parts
sheet Configure
C12  1uF  [C0603]
C13  1uF  [C0603]
C45  1nF  [C0603]
CB20  0.1uF  [C0603]
CB21  0.1uF  [C0603]
CB22  0.1uF  [C0603]
CON3  HEADER10/2.54mm_M
K1  Exit  [STS-B5]
K2  Right  [STS-B5]
K3  Left  [STS-B5]
K4  Enter  [STS-B5]
K5  Dwn  [STS-B5]
K6  Up  [STS-B5]
L16  FB  [0603]
LED1  LED_YELLOW  [LED_0805]
LED2  LED_GREEN  [LED_0805]
LED3  LED_RED  [LED_0805]
Q1  2N3904  [SOT-23BEC]
R22  10K  [R0603]
R23  10K  [R0603]
R24  10K  [R0603]
R25  10K  [R0603]
R26  10K  [R0603]
R27  10K  [R0603]
R28  330  [R0603]
R29  330  [R0603]
R30  330  [R0603]
R31  100K  [R0603]
R32  0  [R0603]
R33  100K  [R0603]
R92  470  [R0603]
RP1  10K-8P4R  [8P4RA]
SW1  DIP-SW2  [DIPSWx2_2.54mm]
SW2  Reset  [STS-B5]
SW3  DIP-SW2  [DIPSWx2_2.54mm]
sheet Expand
CB48  0.1uF  [C0603]
CB49  0.1uF  [C0603]
CB50  0.1uF  [C0603]
CB51  0.1uF  [C0603]
CON23  HEADER15X2/2.54mm_M
CON24  HEADER11X2/2.54mm_M
CT29  10uF  [C0603]
CT30  10uF  [C0603]
CT33  10uF  [C0603]
CT34  10uF  [C0603]
R90  4.7K  [R0603]
R91  4.7K  [R0603]
sheet Memory
C23  NC  [C0603]
C24  NC  [C0603]
CB24  0.1uF  [C0603]
CB25  0.1uF  [C0603]
CON6  B8502A-13SB-HPA (T-Flash Card)  [B8502A-13SB-HPA]
CT20  10uF  [C0603]
CT21  10uF  [C0603]
L9  FB  [0603]
L17  FB  [0603]
R39  10K  [R0603]
R40  10K  [R0603]
R41  10K  [R0603]
R42  0  [R0603]
R43  10K  [R0603]
R44  0  [R0603]
RR1  10K-8P4R  [8P4RA]
RR2  10K-8P4R  [8P4RA]
U7  W25Q128BV  [SOIC16_300]
U8  W55X16  [SOIC8_208_EP]
sheet NUC123ZD4AN0
C14  1uF  [C0603]
C15  1uF  [C0603]
C16  4.7uF  [C0603]
C17  1uF  [C0603]
C18  4.7uF  [C0603]
C19  15pF  [C0603]
C20  15pF  [C0603]
C21  1uF  [C0603]
C22  0.01uF  [C0603]
CB23  0.1uF  [C0603]
CON4  HEADER5/2.54mm_M  [CONS/5X1/2.54]
CON5  USB_MICRO_RECEP.  [MICRO_USB_AB_LS]
L8  FB  [0603]
R34  10K  [R0603]
R35  0  [R0603]
R36  0  [R0603]
R37  27  [R0603]
R38  27  [R0603]
U6  NUC123ZD4AN0  [QFN33_5X5]
X3  12MHz  [TXC7m-3.2x2.5mm]
sheet NUC980DK
U5  NUC980DK  [LQFP-128]
sheet Power Filter
C8  15pF  [C0603]
C9  15pF  [C0603]
C10  15pF  [C0603]
C11  15pF  [C0603]
CB3  0.1uF  [C0603]
CB4  0.1uF  [C0603]
CB5  0.1uF  [C0603]
CB6  0.1uF  [C0603]
CB7  0.1uF  [C0603]
CB8  0.1uF  [C0603]
CB9  0.1uF  [C0603]
CB10  0.1uF  [C0603]
CB11  0.1uF  [C0603]
CB12  0.1uF  [C0603]
CB13  0.1uF  [C0603]
CB14  0.1uF  [C0603]
CB15  0.1uF  [C0603]
CB16  0.1uF  [C0603]
CB17  0.1uF  [C0603]
CB18  0.1uF  [C0603]
CB19  0.1uF  [C0603]
CT12  10uF  [C0603]
CT13  10uF  [C0603]
CT14  10uF  [C0603]
CT15  10uF  [C0603]
CT16  10uF  [C0603]
CT17  10uF  [C0603]
CT18  10uF  [C0603]
CT19  10uF  [C0603]
L4  FB  [0603]
L5  FB  [0603]
L6  FB  [0603]
L7  FB  [0603]
R18  0  [R0603]
R19  12.1K  [R0603]
R20  12.1K  [R0603]
R21  1M  [R0603]
X1  TXC-9H T9 SMD 32.768KHz 30ppm  [XTAL_2P/1.5mm]
X2  12MHz  [TXC7m-3.2x2.5mm]
sheet Power
C1  1uF  [C0603]
C2  470pF  [C0603]
C3  NC  [C0603]
C4  1nF  [C0603]
C5  NC  [C0603]
C6  1nF  [C0603]
C7  NC  [C0603]
CB1  0.1uF  [C0603]
CB2  0.1uF  [C0603]
CON1  DC-PLUG  [POWRJACK\3P]
CON2  HEADER2/2.54mm_M
CT1  10uF  [C0603]
CT2  10uF  [C0603]
CT3  10uF  [C0603]
CT4  10uF  [C0603]
CT5  10uF  [C0603]
CT6  10uF  [C0603]
CT7  10uF  [C0603]
CT8  10uF  [C0603]
CT9  10uF  [C0603]
CT10  10uF  [C0603]
CT11  10uF  [C0603]
D1  SS24A  [403A-03]
D2  SS24A  [403A-03]
D3  RB521S-30  [SOD-523]
D4  RB521S-30  [SOD-523]
L1  4.7uH  [SMTDR43]
L2  4.7uH  [SMTDR43]
L3  4.7uH  [SMTDR43]
LED4  P_Fault  [LED_0805]
LED5  3V3  [LED_0805]
R1  100K  [R0603]
R2  10K  [R0603]
R3  15K  [R0603]
R4  10K  [R0603]
R5  2.7K  [R0603]
R6  0  [R0603]
R7  680K  [R0603]
R8  150K  [R0603]
R9  10K  [R0603]
R10  0  [R0603]
R11  200K  [R0603]
R12  100K  [R0603]
R13  1K  [R0603]
R14  10K  [R0603]
R15  0  [R0603]
R16  120K  [R0603]
R17  120K  [R0603]
R93  0  [R0603]
R94  0  [R0603]
R95  0  [R0603]
U1  APL3211A  [TDFN2x2-8]
U2  ZT7103T  [TSOT-25]
U3  ZT7103T  [TSOT-25]
U4  ZT7103T  [TSOT-25]
sheet RMII_PE
C26  NC  [C0603]
C27  30pF  [C0603]
C28  30pF  [C0603]
C29  0.01uF  [C0603]
C30  0.01uF  [C0603]
C31  0.01uF/2KV  [CK05]
C32  0.01uF/2KV  [CK05]
CB26  0.1uF  [C0603]
CB27  0.1uF  [C0603]
CB28  0.1uF  [C0603]
CB29  0.1uF  [C0603]
CB30  0.1uF  [C0603]
CON7  RJ-45 8P8C_LED R/A  [RJ45\8P\JA\LED]
CT22  10uF  [C0603]
CT23  10uF  [C0603]
CT24  10uF  [C0603]
L10  FB  [L0603]
L11  FB  [L0603]
R45  6.19K  [R0603]
R46  5.1K  [R0603]
R47  5.1K  [R0603]
R48  0  [R0603]
R49  1M  [R0603]
R50  5.1K  [R0603]
R51  330  [R0603]
R52  330  [R0603]
R53  5.1K  [R0603]
R54  10K  [R0603]
R55  75  [R0603]
R56  75  [R0603]
R57  75  [R0603]
R58  75  [R0603]
R59  10K  [R0603]
R60  5.1K  [R0603]
U9  IP101GR  [QFN32]
U10  TS8121C  [ST6200T]
X4  25MHz  [TXC7V-3.2x2.5mm]
sheet RMII_PF
C33  NC  [C0603]
C34  30pF  [C0603]
C35  30pF  [C0603]
C36  0.01uF  [C0603]
C37  0.01uF  [C0603]
C38  0.01uF/2KV  [CK05]
C39  0.01uF/2KV  [CK05]
CB31  0.1uF  [C0603]
CB32  0.1uF  [C0603]
CB33  0.1uF  [C0603]
CB34  0.1uF  [C0603]
CB35  0.1uF  [C0603]
CON8  RJ-45 8P8C_LED R/A  [RJ45\8P\JA\LED]
CT25  10uF  [C0603]
CT26  10uF  [C0603]
CT27  10uF  [C0603]
R61  6.19K  [R0603]
R62  5.1K  [R0603]
R63  5.1K  [R0603]
R64  0  [R0603]
R65  1M  [R0603]
R66  5.1K  [R0603]
R67  330  [R0603]
R68  330  [R0603]
R69  5.1K  [R0603]
R70  10K  [R0603]
R71  75  [R0603]
R72  75  [R0603]
R73  75  [R0603]
R74  75  [R0603]
R75  10K  [R0603]
R76  5.1K  [R0603]
U11  IP101GR  [QFN32]
U12  TS8121C  [ST6200T]
X5  25MHz  [TXC7V-3.2x2.5mm]
sheet UART_A
C40  0.01uF  [C0603]
C41  0.01uF  [C0603]
CB36  0.1uF  [C0603]
CB37  0.47uF  [C0603]
CB38  0.47uF  [C0603]
CB39  0.1uF  [C0603]
CB40  0.47uF  [C0603]
CB41  0.1uF  [C0603]
CB42  0.1uF  [C0603]
CB43  0.47uF  [C0603]
CB44  0.47uF  [C0603]
CB45  0.1uF  [C0603]
CB46  0.47uF  [C0603]
CB47  0.1uF  [C0603]
CON9  DB9_FEMALE  [DB9_FMALE]
CON10  HEADER4/2.54mm_M
CON11  HEADER2/2.54mm_RS485
CON12  DB9_FEMALE  [DB9_FMALE]
CON13  HEADER4/2.54mm_M
CON14  HEADER2/2.54mm_RS485
JP1  HEADER3/2.54mm_M
JP2  HEADER3/2.54mm_M
L12  FB  [0603]
L13  FB  [0603]
R77  120  [R0603]
R78  120  [R0603]
R96  0  [R0603]
R97  0  [R0603]
R98  0  [R0603]
R99  0  [R0603]
R100  0  [R0603]
R101  0  [R0603]
R102  0  [R0603]
R103  0  [R0603]
U13  TRS3232EC  [SOP16/150]
U14  SN65HVD10D  [SOP8/6.0/1.27]
U15  TRS3232EC  [SOP16/150]
U16  SN65HVD10D  [SOP8/6.0/1.27]
sheet UART_B
CON15  HEADER4/2.54mm_M
CON16  HEADER6/2.54mm_M
CON17  HEADER4/2.54mm_M
CON18  HEADER6/2.54mm_M
CON19  HEADER4/2.54mm_M
CON20  HEADER4/2.54mm_M
sheet USB
C42  1uF  [C0603]
C43  0.01uF  [C0603]
C44  0.01uF  [C0603]
CON21  USB_MICRO_RECEP.  [MICRO_USB_AB]
CON21A  USB_MICRO_RECEP.  [MICRO_USB_B]
CON22  USB_TYPE-A_RECAP.  [USB4P]
CT28  10uF  [C0603]
F1  FUSE(6V/1A)  [R0603]
F2  FUSE(6V/1A)  [R0603]
JP3  USB  [Header_2x1_2.54mm]
L14  FB  [0603]
L15  FB  [0603]
Q2  IS2303  [SOT23-GSD]
Q3  IS2303  [SOT23-GSD]
Q4  IS2303  [SOT23-GSD]
Q5  IS2303  [SOT23-GSD]
Q6  IS2304  [SOT23-GSD]
R79  20K  [R0603]
R80  10K  [R0603]
R81  0  [R0603]
R82  0  [R0603]
R83  10K  [R0603]
R84  39K  [R0603]
R85  4.7  [R0603]
R86  4.7  [R0603]
R87  10K  [R0603]
R88  4.7  [R0603]
R89  4.7  [R0603]

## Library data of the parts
C5 C12 C24 C27 C40 CT27 CT30 = CAP_NP_4
C13 C39 CB2 CB25 CB41 CT24 CT34 = CAP_NP_5
C4 C11 C22 C37 C44 C45 CB43 CB51 CT21 CT22 = CAP_NP_3
C8 C21 C43 CB20 CB28 CB34 CB37 CB50 CT6 CT20 = CAP_NP_2
C6 C9 C19 C28 C42 CB21 CB24 CB32 CB38 CB49 = CAP_NP_1
C10 C20 C23 C31 C36 C41 CB22 CT2 CT28 CT33 = CAP_NP
CON3 = HEADER_10
K1 = SW-S_2
K2 = SW-S_3
K3 = SW-S
K4 = SW-S_4
K5 = SW-S_5
K6 = SW-S_6
L7 L8 L11 L13 L15-L17 = INDUCTOR
LED1 = LED_0_1
LED2 = LED_0_2
LED3 = LED_0
Q1 = NPN
R4 R22 R57 R74 R87 R96 = R_6
R2 R23 R55 R65 = R_12
R16 R24 R35 R43 R48 R76 R81 R98 = R_4
R8 R19 R25 R38 R41 R47 R64 R84 R91 R99 = R_1
R15 R26 R53 R66 = R_11
R27 R39 R45 R72 R85 R95 R97 = R_5
R21 R28 R34 R40 R50 R73 R89 R90 R93 R102 = R
R11 R29 R59 R70 R78 R82 = R_8
R10 R30 R60 R75 R77 R83 = R_9
R5 R20 R31 R36 R42 R54 R67 R79 R100 = R_3
R7 R32 R56 R61 R80 R101 = R_7
R9 R33 R52 R71 R86 = R_10
R1 R18 R37 R44 R49 R63 R88 R92 R103 = R_2
RP1 RR1 RR2 = R-PACK8_0_v2
SW1 SW3 = SW_DIP-2_0
SW2 = SW-S_1
C32 C35 CB40 CB48 CT7 = CAP_NP_7
CON23 = HEADER_15X2
CON24 = HEADER_11X2
C29 CB35 CB39 CT11 CT29 = CAP_NP_6
CON6 = B8502A-13SB-HPA_(T-Flash_Card)
L4 L9 L10 L12 L14 = INDUCTOR_1
U7 = W25Q128BV_4
U8 = W55X10_3
C14 = CAP-C_1: Package: 0603
C15 = CAP-C_4: Package: 0603
C16 = CAP-C: Package: 0603
C17 = CAP-C_5: Package: 0603
C18 = CAP-C_2: Package: 0603
CB23 = CAP-C_3: Package: 0603
CON4 = HEADER_5
CON5 = USB_Type_B_0
U6 = NUC101_QFN_0
X2 X3 = Crystal_SMD_2
U5 = NUC970_19
CB3 = CAP-B_8
CB4 = CAP-B_9
CB5 = CAP-B_19
CB6 = CAP-B_20
CB7 = CAP-B_21
CB8 = CAP-B_24
CB9 = CAP-B_1
CB10 = CAP-B_12
CB11 = CAP-B_6
CB12 = CAP-B_5
CB13 = CAP-B_7
CB14 = CAP-B_14
CB15 = CAP-B_18
CB16 = CAP-B_23
CB17 = CAP-B_3
CB18 = CAP-B_22
CB19 = CAP-B_17
CT12 = CAP-B_16
CT13 = CAP-B_11
CT14 = CAP-B_10
CT15 = CAP-B_13
CT16 = CAP-B_15
CT17 = CAP-B
CT18 = CAP-B_2
CT19 = CAP-B_4
L5 = INDUCTOR_2
L6 = INDUCTOR_3
X1 = MA306_SM_2: Vendor: TXC
C1 = CAP_NP_18
C2 C26 C38 CB47 = CAP_NP_8
C3 = CAP_NP_19
C7 = CAP_NP_16
CB1 = CAP_NP_15
CON1 = Power_Jack
CON2 CON11 CON14 = HEADER_2
CB26 CB42 CT1 CT26 = CAP_NP_12
CT3 = CAP_NP_17
C33 CB46 CT4 CT23 = CAP_NP_10
C30 C34 CB36 CT5 = CAP_NP_9
CB29 CB33 CT8 = CAP_NP_14
CB30 CB44 CT9 CT25 = CAP_NP_11
CB27 CB31 CB45 CT10 = CAP_NP_13
D1-D4 = ZENAR_0: Package: D
L1 = INDUCTOR_IRON_1
L2 = INDUCTOR_IRON
L3 = INDUCTOR_IRON_2
LED4 LED5 = LED
R3 = R_19
R6 = R_18
R12 R46 R69 = R_14
R13 = R_17
R14 = R_16
R17 R58 R68 = R_13
R51 R62 R94 = R_15
U1 = APL3203A_1
U2-U4 = ZT7103S_0
CON7 CON8 = RJ45_SHLD_0
U9 = IP101GA_2
U10 U12 = PE-68515_1
X4 X5 = Crystal_SMD_2: Vendor: Aurum
U11 = IP101GA_3
CON9 CON12 = CONNECTOR_DB9_0
CON10 CON20 = HEADER_4_1_1
CON13 CON19 = HEADER_4_1
JP1 JP2 = HEADER_3
U13 U15 = ADM232_0
U14 U16 = W55X10_1
CON15 = HEADER_4_1_3
CON16 = HEADER_4_0_1
CON17 = HEADER_4_1_2
CON18 = HEADER_4_0
CON21 = USB_Type_B_3
CON21A = USB_Type_B_2
CON22 = USB_type_A_connector
F1 F2 = FUSE
JP3 = CON2
Q2-Q5 = MOSFET_P_4
Q6 = MOSFET_N_0

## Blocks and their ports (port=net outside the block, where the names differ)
Schematic07 = schematic Schematic07, on sheet Block Diagram: PC[10:5], VDD33, VSS, PD[7:2], PC12
Schematic10 = schematic Schematic10, on sheet Block Diagram: PD[15:12], VDD33, VSS, PG[14:11]
Schematic03 = schematic Schematic03, on sheet Block Diagram: PA[12:0], PB[8:0], PB13, PC[15:0], PD[15:2], PE[12:0], PF[12:0], PG[1:0], PG3, PG[9:5], PG[15:11], VD12, VD18, VD33, VD33_ADC, VD33_RTC, VSS_ADC, VSS, 32K_IN, 32K_OUT, 12M_IN, 12M_OUT, USB0_DM, USB0_DP, USB0_REXT, USB0_ID, USB1_DP, USB1_DM, USB1_REXT, nRST
Schematic04 = schematic Schematic04, on sheet Block Diagram: 32K_IN, VDD12, VDD33, VSS_ADC, 32K_OUT, 12M_IN, 12M_OUT, VDD18, VD12, VD18, VD33, VD33_ADC, VSS, USB0_REXT, USB1_REXT
Schematic05 = schematic Schematic05, on sheet Block Diagram: PC[2:1], nRST, VDD12, VDD33, VSS, PC[15:13], PB13, PF[12:10], PG[1:0], PG3, PG5, PG[9:8], PG[15:11], nRESET
Schematic11 = schematic Schematic11, on sheet Block Diagram: PA[5:0], VDD33, VSS, PA[12:9], PC[4:3], PB[7:4]
Schematic13 = schematic Schematic13, on sheet Block Diagram: PA[8:6], VDD33, VSS, PB[3:0], PB8, PC[15:0], PD[11:8], PE10, PE12, PG[1:0], PG3, PG[9:6], VD33_ADC, VSS_ADC, VIN
Schematic01 = schematic Schematic01, on sheet Block Diagram: no ports
Schematic02 = schematic Schematic02, on sheet Block Diagram: VDD12, VSS, VDD18, VDD33, VD33_RTC, VIN, 123_USB5V, 980_USB5V
Schematic09 = schematic Schematic09, on sheet Block Diagram: PF[9:0], PHY_DVDD33, PHY_AVDD33, VSS, nRESET
Schematic06 = schematic Schematic06, on sheet Block Diagram: PF[12:11], VDD33, VSS, 123_USB5V
Schematic12 = schematic Schematic12, on sheet Block Diagram: 980_USB5V, PE11, VDD33, VSS, USB0_DP, USB0_DM, USB1_DP, USB1_DM, VIN, USB0_ID
Schematic08 = schematic Schematic08, on sheet Block Diagram: PE[9:0], PHY_DVDD33, VDD33, VSS, PHY_AVDD33, nRESET

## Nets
5VIN: C1.1 CON1.1 CT2.2 D1.2(1) D2.2(1) R1.2 R5.2 U1.1(Vin)
VBUS0_V: F1.2 Q3.2(S) Q4.2(S)
VDD12: C12.2 CT10.1 L6.1 R95.2
VDD18: CT7.1 L7.1 R94.2
VDD33: C18.2 CB23.2 CB24.1 CB25.1 CB39.1 CB41.1 CB45.1 CB47.1 CON3.1 CON4.1 CON6.4(VDD) CON15.3 CON16.3 CON17.3 CON18.3 CON19.3 CON20.3 CON23.27 CON23.28 CON24.19 CON24.20 CT4.1 CT20.1 CT21.1 CT30.1 CT33.1 D3.1(2) L4.1 L10.1 L11.1 R13.2 R28.2 R29.2 R30.2 R31.1 R34.1 R39.2 R40.2 R41.2 R43.1 R83.1 R90.1 R91.1 R93.2 RP1.1(R1) RP1.3(R2) RP1.5(R3) RR1.2(R1) RR1.4(R2) RR1.6(R3) RR1.8(R4) RR2.2(R1) RR2.4(R2) RR2.6(R3) RR2.8(R4) U6.7(LDO_IN_5V) U6.25(AVDD) U7.2(VCC) U8.8(VCC) U13.16(VCC) U14.8(VCC) U15.16(VCC) U16.8(VCC)
VIN: CB1.1 CON23.25 CON23.26 CT1.1 CT3.1 CT6.1 CT9.1 CT29.1 F2.2 Q2.2(S) Q5.2(S) R4.2 R6.1 R9.2 R10.1 R14.2 R15.1 R80.1 U1.8(Vout)
VSS: C1.2 C3.2 C5.2 C7.2 C8.2 C9.2 C10.2 C11.2 C13.1 C14.2 C15.1 C16.1 C17.1 C18.1 C19.2 C20.2 C21.2 C22.2 C23.2 C24.2 C26.2 C27.2 C28.2 C29.2 C30.2 C32.2 C33.2 C34.2 C35.2 C36.2 C37.2 C38.2 C40.1 C41.1 C42.1 C43.2 C44.2 C45.1 CB1.2 CB2.2 CB3.2 CB4.2 CB5.2 CB6.2 CB7.2 CB8.2 CB9.2 CB11.2 CB12.2 CB13.2 CB14.2 CB15.2 CB16.2 CB17.2 CB18.2 CB19.2 CB20.2 CB21.2 CB22.2 CB23.1 CB24.2 CB25.2 CB26.1 CB27.1 CB28.1 CB29.2 CB30.2 CB31.1 CB32.1 CB33.1 CB34.2 CB35.2 CB37.1 CB39.2 CB40.1 CB41.2 CB43.1 CB45.2 CB46.1 CB47.2 CON1.2 CON1.3 CON2.2 CON3.10 CON4.5 CON7.11(LED-) CON8.11(LED-) CON15.4 CON16.4 CON17.4 CON18.4 CON19.4 CON20.4 CON23.29 CON23.30 CON24.21 CON24.22 CT1.2 CT2.1 CT3.2 CT4.2 CT5.2 CT6.2 CT7.2 CT8.2 CT9.2 CT10.2 CT11.2 CT12.2 CT14.2 CT15.2 CT16.2 CT17.2 CT18.2 CT19.2 CT20.2 CT21.2 CT22.2 CT23.2 CT24.2 CT25.2 CT26.2 CT27.2 CT28.1 CT29.2 CT30.2 CT33.2 JP3.2 L8.1 L9.1 L12.2 L13.2 L14.1 L15.1 L17.1 LED5.2(CATHODE) Q1.EMITTER Q6.2(SOURCE) R1.1 R2.2 R3.2 R8.1 R12.2 R17.2 R18.1 R19.2 R20.2 R22.1 R23.1 R24.1 R25.1 R26.1 R27.1 R33.2 R45.1 R53.2 R60.1 R61.1 R69.2 R76.1 R84.1 R87.1 RP1.7(R4) SW2.2 U1.2(GND) U1.9(GND) U2.2(GND) U3.2(GND) U4.2(GND) U5.64(VSS) U5.95(PLL_VSS) U5.128(VSS) U6.8(VSS) U6.32(PVSS) U6.33(VSS) U7.10(GND) U8.4(GND) U8.9(G) U9.33(EPad) U11.33(EPad) U13.15(GND) U14.5(GND) U15.15(GND) U16.5(GND) X2.2(GND) X2.4(GND) X3.2(GND) X3.4(GND) X4.2(GND) X4.4(GND) X5.2(GND) X5.4(GND)
VSS_ADC: CB10.2 CB48.2 CB49.2 CB50.2 CB51.2 CON24.1 CT13.2 CT34.2 R18.2 U5.32(AVSSADC)
12M_IN: C10.1 R21.2 U5.103(XT_IN) X2.1(XIN)
12M_OUT: C11.1 R21.1 U5.104(XT_OUT) X2.3(XOUT)
32K_IN: C8.1 U5.40(X32_IN) X1.2
32K_OUT: C9.1 U5.41(X32_OUT) X1.1
123_USB5V: C16.2 C21.1 CON5.1(V+) D2.1(2) U6.9(VBUS)
980_USB5V: D1.1(2) Q4.3(D) R79.2
nRESET: C13.2 Q1.COLLECTOR R31.2 R32.1 R92.1 SW2.3 U9.32(nRst) U11.32(nRst)
nRST: L16.2 U5.81(nRESET/WDT_nRST)
PA0: CON15.2 U5.2(PA.0/QSPI0_SS1/I2C0_SDA/UART1_RXD/EINT0/TM0_ECNT/CAN3_RXD)
PA1: CON15.1 U5.3(PA.1/EBI_nCS2/EBI_MCLK/I2C0_SCL/UART1_TXD/EINT1/TM1_ECNT/CAN3_TXD)
PA2: CON16.6 U5.4(PA.2/UART6_CTS/I2S_LRCK/SC0_CD/JTAG1_TDO/TM2_ECNT)
PA3: CON16.5 U5.5(PA.3/UART6_RTS/I2S_BCLK/SC0_PWR/JTAG1_TCK/TM3_ECNT)
PA4: CON16.2 U5.6(PA.4/UART6_RXD/I2S_DI/SC0_DAT/JTAG1_TMS/TM4_ECNT)
PA5: CON16.1 U5.7(PA.5/UART6_TXD/I2S_DO/SC0_CLK/JTAG1_TDII/TM5_ECNT)
PA6: CON23.21 U5.8(PA.6/EBI_nCS1/I2S_MCLK/SC0_RST/JTAG1_nTRST)
PA7: CON23.22 U5.14(PA.7/EBI_nWE/UART2_CTS/TM3_EXT)
PA8: CON23.23 U5.15(PA.8/EBI_nRE/UART2_RTS/TM3_TGL)
PA9: CON17.2 U5.16(PA.9/EBI_nCS0/UART2_RXD/TM2_EXT)
PA10: CON17.1 U5.17(PA.10/EBI_ADDR10/UART2_TXD/TM2_TGL)
PA11: CON20.2 U5.18(PA.11/EBI_ADDR9/UART8_RXD/TM4_EXT)
PA12: CON20.1 U5.19(PA.12/EBI_ADDR8/UART8_TXD/TM4_TGL)
PB0: CB48.1 CON24.3 U5.29(PB.0/EBI_ADDR12/UART2_CTS/ADC_AIN0)
PB1: CB49.1 CON24.5 U5.36(PB.1/EBI_ADDR17/I2C3_SDA/I2S_MCLK/CAN2_RXD/TM0_EXT/SPI1_SS1/UART9_TXD/ADC_AIN1)
PB2: CB50.1 CON23.3 CON24.7 U5.38(PB.2/EBI_ADDR2/UART9_RTS/ADC_AIN2)
PB3: CB51.1 CON24.9 U5.37(PB.3/EBI_ADDR18/I2C3_SCL/EINT2/CAN2_TXD/TM0_TGL/SPI0_SS1/UART9_RXD/ADC_AIN3)
PB4: CON18.2 U5.31(PB.4/EBI_ADDR14/I2C1_SCL/I2S_BCLK/USBHL0_DP/UART7_RXD/SPI1_CLK/ADC_AIN4)
PB5: CON18.5 U5.35(PB.5/EBI_ADDR16/I2C2_SCL/I2S_DO/USBHL0_DP/UART7_RTS/SPI1_MISO/ADC_AIN5)
PB6: CON18.1 U5.30(PB.6/EBI_ADDR13/I2C1_SDA/I2S_LRCK/USBHL0_DM/UART7_TXD/SPI1_SS0/ADC_AIN6)
PB7: CON18.6 U5.34(PB.7/EBI_ADDR15/I2C2_SDA/I2S_DI/USBHL0_DM/UART7_CTS/SPI1_MOSI/ADC_AIN7)
PB8: CON24.13 U5.42(PB.8/EBI_ADDR11/I2C2_SCL/CAN2_RXD/UART8_TXD/SD0_nCD/TM0_EXT)
PB13: LED2.2 U5.93(PB.13/EINT2/TM4_TGL/PWM02/UART3_TXD/USBHL4_DP/EBI_DATA0)
PC0: CON23.5 CON24.15 U5.44(PC.0/EBI_DATA0/I2C2_SDA/CAN2_TXD/UART8_RXD/SPI0_SS1/TM0_TGL)
PC1: CON23.6 K1.1 K3.1 K5.1 U5.45(PC.1/EBI_DATA1/NAND_nCS0/UART7_TXD)
PC2: CON23.7 K2.1 K4.1 K6.1 U5.46(PC.2/EBI_DATA2/NAND_nWP/UART7_RXD)
PC3: CON19.1 CON23.8 U5.47(PC.3/EBI_DATA3/VCAP0_CLKO/NAND_ALE/I2C1_SCL/UART3_TXD/CAN0_RXD)
PC4: CON19.2 CON23.9 U5.48(PC.4/EBI_DATA4/VCAP0_PCLK/NAND_CLE/I2C1_SDA/UART3_RXD/SPI0_MOSI/CAN0_TXD)
PC5: CON6.3(CMD) CON23.10 RR2.5(R3) U5.49(PC.5/EBI_DATA5/VCAP0_HSYNC/NAND_nWE/SPI0_SS0/SD0_CMD/UART1_TXD/eMMC0_CMD)
PC6: CON23.11 R44.2 U5.50(PC.6/EBI_DATA6/VCAP0_VSYNC/NAND_nRE/SC1_RST/SPI0_CLK/SD0_CLK/UART1_RXD/eMMC0_CLK)
PC7: CON6.7(DAT0) CON23.12 RR1.1(R1) U5.51(PC.7/EBI_DATA7/VCAP0_FIELDI/NAND_RDY0/SC1_CLK/SPI0_MOSI/SD0_DATA0/UART1_RTS/eMMC0_DATA0)
PC8: CON6.8(DAT1) CON23.13 RR1.3(R2) U5.52(PC.8/EBI_DATA8/VCAP0_DATA0/NAND_DATA0/SC1_DAT/SPI0_MISO/SD0_DATA1/UART1_CTS/eMMC0_DATA0)
PC9: CON6.1(DAT2) CON23.14 RR2.1(R1) U5.53(PC.9/EBI_DATA9/VCAP0_DATA1/NAND_DATA1/SC1_PWR/SD0_DATA2/UART4_TXD/eMMC0_DATA2)
PC10: CON6.2(DAT3) CON23.15 RR2.3(R2) U5.54(PC.10/EBI_DATA10/VCAP0_DATA2/NAND_DATA2/SC1_CD/SD0_DATA3/UART4_RXD/eMMC0_DATA3)
PC11: CON23.16 U5.55(PC.11/EBI_DATA11/VCAP0_DATA3/NAND_DATA3/SC0_RST)
PC12: CON6.9(CD) CON23.17 RR1.5(R3) U5.56(PC.12/EBI_DATA12/VCAP0_DATA4/NAND_DATA4/SC0_CLK/SD0_nCD/UART8_TXD)
PC13: CB20.1 CON23.18 K1.3 K2.3 U5.57(PC.13/EBI_DATA13/VCAP0_DATA5/NAND_DATA5/SC0_DAT/UART8_RXD)
PC14: CB21.1 CON23.19 K3.3 K4.3 U5.58(PC.14/EBI_DATA14/VCAP0_DATA6/NAND_DATA6/SC0_PWR/SPI0_MOSI/UART8_RTS)
PC15: CB22.1 CON23.20 K5.3 K6.3 U5.59(PC.15/EBI_DATA15/VCAP0_DATA7/NAND_DATA7/SC0_CD/UART8_CTS)
PD2: R41.1 U5.61(PD.2/QSPI0_SS0/UART3_TXD/TM4_EXT) U7.7(CS) U8.1(/CS)
PD3: R42.2 U5.62(PD.3/QSPI0_CLK/UART3_RXD/TM4_TGL)
PD4: U5.63(PD.4/QSPI0_MOSI0/UART3_RTS/TM5_EXT) U7.15(Di/D0) U8.5(Di/D0)
PD5: U5.65(PD.5/QSPI0_MISO0/UART3_CTS/TM5_TGL) U7.8(Do/D1) U8.2(Do/D1)
PD6: R39.1 U5.66(PD.6/QSPI0_MOSI1/UART2_TXD/TM0_ECNT/CAN0_RXD) U7.9(Wp/D2) U8.3(Wp/D2)
PD7: R40.1 U5.67(PD.7/QSPI0_MISO1/UART2_RXD/TM1_ECNT/CAN0_TXD) U7.1(Hld/D3) U8.7(Hld/D3)
PD8: CON24.2 U5.68(PD.8/SPI0_SS0/UART6_CTS/TM2_ECNT)
PD9: CON24.4 U5.69(PD.9/SPI0_CLK/UART6_RTS/TM3_ECNT)
PD10: CON24.6 U5.70(PD.10/SPI0_MOSI/UART6_TXD/TM4_ECNT)
PD11: CON24.8 U5.71(PD.11/SPI0_MISOI/UART6_RXD/TM5_ECNT)
PD12: R96.1 U5.72(PD.12/UART4_TXD/TM2_TGL/CAN2_RXD/PWM00/EBI_DATA1)
PD13: R97.1 U5.73(PD.13/UART4_RXD/TM2_EXT/CAN2_TXD/PWM01/EBI_DATA2)
PD14: R98.1 U5.74(PD.14/UART4_RTS/TM3_TGL/I2C3_SCL/CAN1_RXD/USBHL0_DM/PWM02/EBI_DATA3)
PD15: R99.1 U5.75(PD.15/UART4_CTS/TM3_EXT/I2C3_SDA/CAN1_TXD/USBHL0_DP/PWM03/EBI_DATA4)
PE0: R47.2 U5.105(PE.0/RMII0_RXERR/CAN0_RXD/UART4_CTS/USBHL1_DM/VCAP1_HSYNC) U9.21(RxEr/Int32)
PE1: R60.2 U5.106(PE.1/RMII0_CRSDV/CAN0_TXD/UART4_RTS/USBHL1_DP/VCAP1_VSYNC) U9.19(RxDV/CRS_DV)
PE2: U5.107(PE.2/RMII0_RXD1/CAN1_RXD/UART4_RXD/USBHL2_DM/VCAP1_DATA0) U9.17(RxD1)
PE3: U5.108(PE.3/RMII0_RXD0/CAN1_TXD/UART4_TXD/USBHL2_DP/VCAP1_DATA1) U9.18(RxD0)
PE4: R48.1 U5.109(PE.4/RMII0_REFCLK/CAN2_RXD/UART9_CTS/USBHL3_DM/VCAP1_DATA2) U9.14(RxClk/50M_Clko)
PE5: U5.110(PE.5/RMII0_TXEN/CAN2_TXD/UART9_RTS/USBHL3_DP/VCAP1_DATA3) U9.5(TxEn)
PE6: U5.111(PE.6/RMII0_TXD1/CAN3_RXD/UART9_RXD/USBHL4_DM/VCAP1_DATA4) U9.8(TxD1)
PE7: U5.112(PE.7/RMII0_TXD0/CAN3_TXD/UART9_TXD/USBHL4_DP/VCAP1_DATA5) U9.9(TxD0)
PE8: R46.2 U5.113(PE.8/RMII0_MDIO/UART6_RXD/USBHL5_DM/VCAP1_DATA6) U9.23(MDIO)
PE9: U5.114(PE.9/RMII0_MDC/UART6_TXD/USBHL5_DP/VCAP1_DATA7) U9.22(MDC)
PE10: CON24.17 R90.2 U5.115(PE.10/USB_OVC/CAN3_RXD/UART9_RXD/PWM12/EINT2/I2C0_SDA/VCAP1_FIELD)
PE11: R79.1 R84.2 U5.116(PE.11/USB0_VBUSVLD)
PE12: CON24.18 R91.2 U5.117(PE.12/USBH_PWREN/CAN3_TXD/UART9_TXD/PWM13/EINT3/I2C0_SCL/VCAP1_CLKO)
PF0: R63.2 U5.86(PF.0/RMII1_RXERR/SD1_CMD/TM0_ECNT/SC1_RST/UART7_CTS/USBHL1_DM/eMMC1_CMD/EBI_DATA5) U11.21(RxEr/Int32)
PF1: R76.2 U5.87(PF.1/RMII1_CRSDV/SD1_CLK/TM1_ECNT/SC1_CLK/UART7_RTS/USBHL1_DP/eMMC1_CLK/EBI_DATA6) U11.19(RxDV/CRS_DV)
PF2: U5.88(PF.2/RMII1_RXD1/SD1_DATA0/TM2_ECNT/SC1_DAT/UART7_RXD/USBHL2_DM/eMMC1_DATA0/EBI_DATA7) U11.17(RxD1)
PF3: U5.89(PF.3/RMII1_RXD0/SD1_DATA1/TM3_ECNT/SC1_PWR/UART7_TXD/USBHL2_DP/eMMC1_DATA1/EBI_DATA8) U11.18(RxD0)
PF4: R64.1 U5.90(PF.4/RMII1_REFCLK/SD1_DATA2/TM4_ECNT/SC1_CD/UART3_CTS/USBHL3_DM/eMMC1_DATA2/EBI_DATA9) U11.14(RxClk/50M_Clko)
PF5: U5.91(PF.5/RMII1_TXEN/SD1_DATA3/TM5_ECNT/PWM00/UART3_RTS/USBHL3_DP/eMMC1_DATA3/EBI_DATA10) U11.5(TxEn)
PF6: U5.92(PF.6/RMII1_TXD1/SD1_nCD/TM4_EXT/PWM01/UART3_RXD/USBHL4_DM/EBI_DATA11) U11.8(TxD1)
PF7: U5.96(PF.7/RMII1_TXD0/UART1_CTS/TM5_EXT/PWM02/UART3_TXD/USBHL4_DP/EBI_DATA12) U11.9(TxD0)
PF8: R62.2 U5.97(PF.8/RMII1_MDIO/UART1_RTS/TM1_TGL/PWM03/USBHL5_DM/EBI_DATA13) U11.23(MDIO)
PF9: U5.98(PF.9/RMII1_MDC/UART1_RXD/TM1_EXT/PWM10/USBHL5_DP/EBI_DATA14) U11.22(MDC)
PF10: LED3.2 U5.99(PF.10/UART1_TXD/TM5_TGL/PWM11/VCAP1_PCLK/EBI_DATA15)
PF11: CON3.9 R36.1 U5.100(PF.11/UART0_RXD)
PF12: CON3.8 R35.1 U5.101(PF.12/UART0_TXD)
PG0: CON23.1 SW1.1(A1) U5.28(PG.0/EBI_ADDR0/UART2_RXD/CLK_OUT/PWM00/CFG.0_PwrOnSet0)
PG1: CON23.2 SW1.2(A2) U5.27(PG.1/EBI_ADDR1/UART2_TXD/PWM01/CFG.1_PwrOnSet1)
PG3: CON23.4 R24.2 U5.26(PG.3/EBI_ADDR3/UART2_RTS/PWM03/CFG.3_PwrOnSet3)
PG5: R25.2 U5.25(PG.5/EBI_ADDR12/UART5_RTS/CFG.5_PwrOnSet5)
PG6: CON24.10 U5.24(PG.6/EBI_ADDR4/UART5_RXD/PWM10/CFG.6_PwrOnSet6)
PG7: CON24.12 U5.23(PG.7/EBI_ADDR5/UART5_TXD/PWM11/CFG.7_PwrOnSet7)
PG8: CON24.14 SW3.1(A1) U5.22(PG.8/EBI_ADDR6/UART8_RTS/PWM12/CFG.8_PwrOnSet8)
PG9: CON24.16 SW3.2(A2) U5.21(PG.9/EBI_ADDR7/UART8_CTS/PWM13/CFG.9_PwrOnSet9)
PG11: CON3.6 R103.1 U5.76(PG.11/SPI1_SS0/TM1_TGL/CAN0_RXD/UART5_CTS/PWM10/JTAG0_TDO)
PG12: CON3.5 R102.1 RP1.8(R4) U5.77(PG.12/SPI1_CLK/TM1_EXT/CAN0_TXD/UART5_RTS/PWM11/JTAG0_TCK)
PG13: CON3.4 R101.1 RP1.6(R3) U5.78(PG.13/SPI1_MOSI/CAN1_RXD/UART5_RXD/PWM12/JTAG0_TMS)
PG14: CON3.3 R100.1 RP1.4(R2) U5.79(PG.14/SPI1_MISO/CAN1_TXD/UART5_TXD/PWM13/JTAG0_TDI)
PG15: CON3.2 LED1.2 RP1.2(R1) U5.80(PG.15/SPI0_SS1/SPI1_SS1/EINT3/JTAG0_nTRST)
PHY_AVDD33: CB28.2 CB31.2 CT24.1 CT25.1 L11.2 U9.31(AVD33) U11.31(AVD33)
PHY_DVDD33: CB27.2 CB32.2 CON7.10(LED+) CON8.10(LED+) CT23.1 CT26.1 L10.2 R46.1 R47.1 R50.1 R54.2 R59.2 R62.1 R63.1 R66.1 R70.2 R75.2 U9.13(IOVDD) U11.13(IOVDD)
Schematic06/12M_I: C19.1 U6.30(XT_IN) X3.1(XIN)
Schematic06/12M_O: C20.1 U6.29(XT_OUT) X3.3(XOUT)
Schematic06/D+: R38.2 U6.12(D+)
Schematic06/D-: R37.2 U6.11(D-)
Schematic06/ICE_CLK: CON4.3 U6.24(ICE_CLK)
Schematic06/ICE_DAT: CON4.2 U6.23(ICE_DAT)
Schematic06/RES: C15.2 CON4.4 R34.2 U6.31(RESET#)
Schematic06/UR0_RX: R36.2 U6.5(TX1/PB.5)
Schematic06/UR0_TX: R35.2 U6.4(RX1/PB.4)
Schematic07/CLK: C23.1 R42.1 U7.16(CLK) U8.6(CLK)
Schematic08/E_COL: R54.1 U9.4(Col/RMII)
Schematic08/E_CRS: R59.1 U9.20(CRS/LEDMod)
Schematic08/E_ETH_XI: C27.1 R49.2 U9.2(Xi) X4.1(XIN)
Schematic08/E_ETH_XO: C28.1 R49.1 U9.3(Xo) X4.3(XOUT)
Schematic08/E_MDI_RN: U9.26(MDiRn) U10.8(RD-)
Schematic08/E_MDI_RP: U9.27(MDiRp) U10.6(RD+)
Schematic08/E_MDI_TN: U9.29(MDiTn) U10.3(TD-)
Schematic08/E_MDI_TP: U9.30(MDiTp) U10.1(TD+)
Schematic08/E_PHY_AD0: R50.2 R52.1 U9.11(LED0/PhyAD0)
Schematic08/E_PHY_AD3: R51.1 R53.1 U9.12(LED3/PhyAD3)
Schematic08/E_REG_OUT: CB26.2 CT22.1 U9.28(RegOut)
Schematic08/E_RX+: CON7.3(RX+) U10.11(RX+)
Schematic08/E_RX-: CON7.6(RX-) U10.9(RX-)
Schematic08/E_RX_CLK: C26.1 R48.2 U9.10(TxClk/50MClki)
Schematic08/E_TX+: CON7.1(TX+) U10.16(TX+)
Schematic08/E_TX-: CON7.2(TX-) U10.14(TX-)
Schematic09/F_COL: R70.1 U11.4(Col/RMII)
Schematic09/F_CRS: R75.1 U11.20(CRS/LEDMod)
Schematic09/F_ETH_XI: C34.1 R65.2 U11.2(Xi) X5.1(XIN)
Schematic09/F_ETH_XO: C35.1 R65.1 U11.3(Xo) X5.3(XOUT)
Schematic09/F_MDI_RN: U11.26(MDiRn) U12.8(RD-)
Schematic09/F_MDI_RP: U11.27(MDiRp) U12.6(RD+)
Schematic09/F_MDI_TN: U11.29(MDiTn) U12.3(TD-)
Schematic09/F_MDI_TP: U11.30(MDiTp) U12.1(TD+)
Schematic09/F_PHY_AD0: R66.2 R68.1 U11.11(LED0/PhyAD0)
Schematic09/F_PHY_AD3: R67.1 R69.1 U11.12(LED3/PhyAD3)
Schematic09/F_REG_OUT: CB33.2 CT27.1 U11.28(RegOut)
Schematic09/F_RX+: CON8.3(RX+) U12.11(RX+)
Schematic09/F_RX-: CON8.6(RX-) U12.9(RX-)
Schematic09/F_RX_CLK: C33.1 R64.2 U11.10(TxClk/50MClki)
Schematic09/F_TX+: CON8.1(TX+) U12.16(TX+)
Schematic09/F_TX-: CON8.2(TX-) U12.14(TX-)
Schematic10/RS485_A4: CON11.1 R77.1 U14.6(A)
Schematic10/RS485_A5: CON14.1 R78.1 U16.6(A)
Schematic10/RS485_B4: CON11.2 R77.2 U14.7(B)
Schematic10/RS485_B5: CON14.2 R78.2 U16.7(B)
Schematic10/UR4CT: CON9.7 U13.8(R2in)
Schematic10/UR4CTS: CON10.4 R99.2 U13.9(R2o)
Schematic10/UR4RT: CON9.8 U13.7(T2o)
Schematic10/UR4RTS: CON10.3 R98.2 U13.10(T2in) U14.2(/RE) U14.3(DE)
Schematic10/UR4RX: CON9.3 U13.13(R1in)
Schematic10/UR4RXD: CON10.2 JP1.2 R97.2
Schematic10/UR4RXD_232: JP1.1 U13.12(R1o)
Schematic10/UR4RXD_485: JP1.3 U14.1(R)
Schematic10/UR4TX: CON9.2 U13.14(T1o)
Schematic10/UR4TXD: CON10.1 R96.2 U13.11(T1in) U14.4(D)
Schematic10/UR5CT: CON12.7 U15.8(R2in)
Schematic10/UR5CTS: CON13.4 R103.2 U15.9(R2o)
Schematic10/UR5RT: CON12.8 U15.7(T2o)
Schematic10/UR5RTS: CON13.3 R102.2 U15.10(T2in) U16.2(/RE) U16.3(DE)
Schematic10/UR5RX: CON12.3 U15.13(R1in)
Schematic10/UR5RXD: CON13.2 JP2.2 R101.2
Schematic10/UR5RXD_232: JP2.1 U15.12(R1o)
Schematic10/UR5RXD_485: JP2.3 U16.1(R)
Schematic10/UR5TX: CON12.2 U15.14(T1o)
Schematic10/UR5TXD: CON13.1 R100.2 U15.11(T1in) U16.4(D)
Schematic12/USB0_DH: CON21.4(ID) CON21A.4(ID) JP3.1 Q5.1(G) R81.2
USB0_DM: R85.2 U5.124(USB0_DM)
USB0_DP: R86.2 U5.125(USB0_DP)
USB0_ID: Q6.3(DRAIN) R83.2 U5.1(USB0_ID)
USB0_REXT: R19.1 U5.127(USB0_REXT)
USB1_DM: R88.2 U5.119(USB1_DM)
USB1_DP: R89.2 U5.120(USB1_DP)
USB1_REXT: R20.1 U5.122(USB1_REXT)
VD12: CB11.1 CB12.1 CB13.1 CB14.1 CB15.1 CB16.1 CB17.1 CT14.1 CT15.1 CT16.1 CT17.1 L6.2 U5.10(VDD) U5.13(VDD) U5.43(VDD) U5.82(VDD) U5.94(VDD) U5.118(VDD) U5.123(USB0_VDD)
VD18: CB18.1 CB19.1 CT18.1 CT19.1 L7.2 U5.11(MVDD) U5.12(MVDD) U5.83(MVDD) U5.84(MVDD)
VD33: CB3.1 CB4.1 CB5.1 CB6.1 CB7.1 CB8.1 CB9.1 CT12.1 L4.2 L5.1 U5.9(VDDIO) U5.20(VDDIO) U5.60(VDDIO) U5.85(VDDIO) U5.102(VDDIO) U5.121(USB1_VDD33) U5.126(USB0_VDD33)
VD33_ADC: CB10.1 CON24.11 CT13.1 CT34.1 L5.2 U5.33(AVDDADC)
VD33_RTC: CB2.1 D3.2(1) D4.2(1) U5.39(VBAT33)
N16822750: LED4.1(ANODE) R5.1
N16822794: LED5.1(ANODE) R13.1
Schematic02/N16778107: LED4.2(CATHODE) U1.4(#Fault)
Schematic02/N16778127: R3.1 U1.7(Ilimit)
Schematic02/N16778208: R2.1 U1.5(#En) U1.6(Bat)
Schematic02/N16784849: CON2.1 D4.1(2)
Schematic02/N16811538: C4.1 CT8.1 L2.2 R11.2 R94.1
Schematic02/N16811542: C2.1 R7.1 R8.2 U2.5(FB)
Schematic02/N16811544: C6.1 CT11.1 L3.2 R16.2 R95.1
Schematic02/N16811556: R15.2 U4.4(Vin)
Schematic02/N16811568: R10.2 U3.4(Vin)
Schematic02/N16811584: C5.1 R9.1 U3.1(EN)
Schematic02/N16811635: C2.2 CT5.1 L1.2 R7.2 R93.1
Schematic02/N16811664: C4.2 R11.1 R12.1 U3.5(FB)
Schematic02/N16811666: C7.1 R14.1 U4.1(EN)
Schematic02/N16811688: L3.1 U4.3(SW)
Schematic02/N16811702: L2.1 U3.3(SW)
Schematic02/N16811722: C6.2 R16.1 R17.1 U4.5(FB)
Schematic02/N16811955: R6.2 U2.4(Vin)
Schematic02/N16811975: L1.1 U2.3(SW)
Schematic02/N16811977: C3.1 R4.1 U2.1(EN)
Schematic05/N16777810: CON3.7 R32.2
Schematic05/N16803129: C12.1 Q1.BASE R33.1
Schematic05/N16807178: LED2.1 R29.1
Schematic05/N16808744: LED3.1 R30.1
Schematic05/N16809522: LED1.1 R28.1
Schematic05/N16830171: R22.2 SW1.3(B2)
Schematic05/N16830176: R23.2 SW1.4(B1)
Schematic05/N16837800: C45.2 L16.1 R92.2
Schematic05/N16843757: R26.2 SW3.3(B2)
Schematic05/N16843854: R27.2 SW3.4(B1)
Schematic06/N16765798: C17.2 U6.6(LDO_OUT)
Schematic06/N16779489: C22.1 CON5.6(\) CON5.7(\) CON5.8(\) CON5.9(\)
Schematic06/N16779536: CON5.2(D-) R37.1
Schematic06/N16779538: CON5.3(D+) R38.1
Schematic06/N16797547: CON5.5(GND) L8.2
Schematic06/N17128688: C14.1 U6.10(USB_LDO_OUT)
Schematic07/N16791552: R43.2 U7.3(/Rst)
Schematic07/N16793505: CON6.10(GND) CON6.11(GND) CON6.12(GND) CON6.13(GND) L17.2
Schematic07/N16793534: CON6.6(VSS) L9.2
Schematic07/N16793602: C24.1 CON6.5(CLK) R44.1
Schematic08/N43037: C30.1 CB30.1 U10.2(CT)
Schematic08/N43057: C31.1 C32.1 CON7.13(Shield) CON7.14(Shield)
Schematic08/N43187: R57.2 U10.10(CT)
Schematic08/N43211: R58.2 U10.15(CT)
Schematic08/N43221: CON7.7(NC) CON7.8(NC) R55.2
Schematic08/N43237: CON7.4(NC) CON7.5(NC) R56.2
Schematic08/N44057: C29.1 CB29.1 U10.7(CT)
Schematic08/N44589: R45.2 U9.25(Iset)
Schematic08/N44889: CON7.9(LED-) R52.2
Schematic08/N45241: C31.2 R55.1 R56.1 R57.1 R58.1
Schematic08/N78875: CON7.12(LED+) R51.2
Schematic09/N43037: C37.1 CB35.1 U12.2(CT)
Schematic09/N43057: C38.1 C39.1 CON8.13(Shield) CON8.14(Shield)
Schematic09/N43187: R73.2 U12.10(CT)
Schematic09/N43211: R74.2 U12.15(CT)
Schematic09/N43221: CON8.7(NC) CON8.8(NC) R71.2
Schematic09/N43237: CON8.4(NC) CON8.5(NC) R72.2
Schematic09/N44057: C36.1 CB34.1 U12.7(CT)
Schematic09/N44589: R61.2 U11.25(Iset)
Schematic09/N44889: CON8.9(LED-) R68.2
Schematic09/N45241: C39.2 R71.1 R72.1 R73.1 R74.1
Schematic09/N16824163: CON8.12(LED+) R67.2
Schematic10/N04684: C40.2 CON9.10 CON9.11
Schematic10/N16170292: CB38.1 U13.5(C2-)
Schematic10/N16170296: CB36.1 U13.3(C1-)
Schematic10/N16170300: CB36.2 U13.1(C1+)
Schematic10/N16170304: CB38.2 U13.4(C2+)
Schematic10/N16170322: CB37.2 U13.2(V+)
Schematic10/N16170344: CB40.2 U13.6(V-)
Schematic10/N16482916: CB44.1 U15.5(C2-)
Schematic10/N16482920: CB42.1 U15.3(C1-)
Schematic10/N16482924: CB42.2 U15.1(C1+)
Schematic10/N16482928: CB44.2 U15.4(C2+)
Schematic10/N16482942: CB43.2 U15.2(V+)
Schematic10/N16482964: CB46.2 U15.6(V-)
Schematic10/N16486886: CON9.5 L12.1
Schematic10/N16488017: CON12.5 L13.1
Schematic10/N16488021: C41.2 CON12.10 CON12.11
Schematic12/N16468542: CON21.5(GND) CON21A.5(GND) L14.2
Schematic12/N16468590: CON22.4(GND) L15.2
Schematic12/N16468626: Q2.3(D) Q3.3(D)
Schematic12/N16468630: C42.2 CON21.1(V+) CON21A.1(V+) F1.1
Schematic12/N16468634: CON22.1(VBUS) CT28.2 F2.1
Schematic12/N16468642: Q2.1(G) Q3.1(G) R80.2 R81.1
Schematic12/N16468682: Q5.3(D) Q6.1(GATE) R82.2 R87.2
Schematic12/N16468710: Q4.1(G) R82.1
Schematic12/N16468752: C43.1 CON21.6(\) CON21.7(\) CON21.8(\) CON21.9(\) CON21.10(\) CON21.11(\) CON21A.6(\) CON21A.7(\) CON21A.8(\) CON21A.9(\) CON21A.10(\) CON21A.11(\)
Schematic12/N16469044: CON22.2(D-) R88.1
Schematic12/N16469048: CON22.3(D+) R89.1
Schematic12/N16469082: C44.1 CON22.5(Shield) CON22.6(Shield)
Schematic12/N16478913: CON21.3(D+) CON21A.3(D+) R86.1
Schematic12/N16478926: CON21.2(D-) CON21A.2(D-) R85.1

Not connected (* = marked no-connect by the designer): CON5 4(ID); CON9 1* 4* 6* 9*; CON12 1* 4* 6* 9*; CON23 24*; K1 2 4*; K2 2 4*; K3 2 4*; K4 2 4*; K5 2 4*; K6 2 4*; RR1 7(R4)*; RR2 7(R4)*; SW2 1* 4*; U1 3(N.C.)*; U6 1(INT0/PB.14)* 2(I2C1_SCL/PA.11)* 3(I2C1_SDA/PA.10)* 13(MOSI0_0/PC.3)* 14(MISO0_0/PC.2)* 15(SPI0_CLK/PC.1)* 16(SPI0_CS0/PC.0)* 17(MOSI1_1/PC.13)* 18(MISO1_1/PC.12)* 19(MOSI1_0/PC.11)* 20(MISO1_0/PC.10)* 21(SPI1_CLK/PC.9)* 22(SPI1_CS0/PC.8)* 26(SPI2_CLK/PD.1)* 27(MISO2_0/PD.2)* 28(MOSI2_0/PD.3)*; U7 4(NC)* 5(NC)* 6(NC)* 11(NC)* 12(NC)* 13(NC)* 14(NC)*; U9 1(TxEr/FxSD)* 6(TxD3)* 7(TxD2)* 15(RxD3)* 16(RxD2)* 24(TestOn); U10 4(NC)* 5(NC)* 12(NC)* 13(NC)*; U11 1(TxEr/FxSD)* 6(TxD3)* 7(TxD2)* 15(RxD3)* 16(RxD2)* 24(TestOn); U12 4(NC)* 5(NC)* 12(NC)* 13(NC)*

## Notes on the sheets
sheet 1
- nuvoTon
- NuDesign
- Order No. NK-980ETH2P
- http://www.nuvoton.com/board/numaker-nuc980-serial-server
sheet 2
- QSPI0_Flash
- SD0/eMMC0
sheet 3
- Ethernet0_PE
sheet 5
- Ethernet1_PF
sheet 6
- RS232_4
- C.F.
- RS232_4
- RS232_4
- RX4
- TX4
- RS485_4
- RT4
- CT4
- RS485_4
- A4
- B4
- RS232_5
- C.F.
- RS232_5
- RS232_5
- TX5
- RX5
- CT5
- RT5
- RS485_5
- RS485_5
- A5
- B5
sheet 7
- PIN
- FUNCTION
- PIN
- FUNCTION
- PIN
- FUNCTION
- PIN
- FUNCTION
- PIN
- FUNCTION
- PIN
- FUNCTION
- PIN
- FUNCTION
- PA0
- UART1_RXD
- PB0
- ADC_AIN[0]
- PC0
- CAN2_TXD
- PD2
- QSPI0_SS0
- PE0
- RMII0_RXERR
- PF0
- RMII1_RXERR
- PG0
- EBI_ADDR0
- EBI_DATA0
- CFG[0]
- PA1
- UART1_TXD
- PB1
- ADC_AIN[1]
- Col0
- PD3
- QSPI0_CLK
- PE1
- RMII0_CRSDV
- PF1
- RMII1_CRSDV
- EBI_ADDR1
- PC1
- PG1
- ADC_AIN[2]
- EBI_DATA1
- CFG[1]
- PA2
- UART6_CTS
- PB2
- EBI_ADDR2
- Col1
- PD4
- QSPI0_D0
- PE2
- RMII0_RXD1
- PF2
- RMII1_RXD1
- EBI_ADDR3
- PC2
- PG3
- PA3
- UART6_RTS
- EBI_DATA2
- PD5
- QSPI0_D1
- PE3
- RMII0_RXD0
- PF3
- RMII1_RXD0
- CFG[3]
- PB3
- ADC_AIN[3]
- UART3_TXD
- PA4
- UART6_RXD
- PB4
- UART7_RXD
- PC3
- EBI_DATA3
- PD6
- QSPI0_D2
- PE4
- RMII0_REFCLK
- PF4
- RMII1_REFCLK
- PG5
- CFG[5]
- PA5
- UART6_TXD
- UART3_RXD
- PD7
- QSPI0_D3
- PE5
- RMII0_TXEN
- PF5
- RMII1_TXEN
- PG6
- PWM10
- PB5
- UART7_RTS
- PC4
- EBI_DATA4
- PA6
- EBI_nCS1
- PD8
- SPI0_SS0
- PE6
- RMII0_TXD1
- PF6
- RMII1_TXD1
- PG7
- PWM11
- PB6
- UART7_TXD
- PC5
- SD0_CMD
- PWM12
- PA7
- EBI_nWE
- EBI_DATA5
- PD9
- SPI0_CLK
- PE7
- RMII0_TXD0
- PF7
- RMII1_TXD0
- PG8
- PB7
- UART7_CTS
- CFG[8]
- SD0_CLK
- PA8
- EBI_nRE
- PC6
- PD10
- SPI0_DO
- PE8
- RMII0_MDIO
- PF8
- RMII1_MDIO
- PWM13
- PB8
- CAN2_RXD
- EBI_DATA6
- PG9
- CFG[9]
- PA9
- UART2_RXD
- SD0_DATA0
- PD11
- SPI0_DI
- PE9
- RMII0_MDC
- PF9
- RMII1_MDC
- PB13
- LED2
- PC7
- UART5_CTS
- EBI_DATA7
- PG11
- PA10
- UART2_TXD
- PD12
- UART4_TXD
- PE10
- I2C0_SDA
- PF10
- LED3
- JTAG0_TDO
- SD0_DATA1
- PA11
- UART8_RXD
- PC8
- EBI_DATA8
- PD13
- UART4_RXD
- PE11
- USB0_VBUSVLD
- PF11
- UART0_RXD
- PG12
- UART5_RTS
- JTAG0_TCK
- SD0_DATA2
- PA12
- UART8_TXD
- PC9
- PD14
- UART4_RTS
- PE12
- I2C0_SCL
- PF12
- UART0_TXD
- UART5_RXD
- EBI_DATA9
- PG13
- SD0_DATA3
- PD15
- UART4_CTS
- JTAG0_TMS
- PC10
- UART5_TXD
- EBI_DATA10
- PG14
- JTAG0_TDI
- LED1
- PC11
- JTAG0_NTRST
- EBI_DATA11
- PG15
- LED1
- SD0_nCD
- PC12
- EBI_DATA12
- PC13
- Row0
- EBI_DATA13
- Row1
- PC14
- EBI_DATA14
- Row2
- PC15
- EBI_DATA15
sheet 8
- 5V IN
- VDD33
- P_Fault
- VDD18
- RTC Battery 3.3V
- +
- -
- VDD12
sheet 9
- RS232_6
- RS232_1
- TX6
- TX1
- RX6
- RX1
- VD33
- VD33
- VSS
- VSS
- RT6
- CT6
- RS232_2
- RS232_7
- TX2
- TX7
- RX2
- RX7
- VD33
- VD33
- VSS
- RT7
- VSS
- CT7
- RS232_8
- RS232_3
- TX8
- TX3
- RX8
- RX3
- VD33
- VD33
- VSS
- VSS
sheet 10
- Power On Setting
- K1
- K2
- PG1
- PG0
- Booting from
- K3
- K4
- ON(0)
- ON(0)
- USB
- ON(0)
- OFF(1)
- SD/eMMC
- OFF(1)
- ON(0)
- NAND Flash
- OFF(1)
- OFF(1)
- QSPI Flash_0
- K5
- K6
- PG3
- Watch Dog
- ON(0)
- OFF
- OFF(1)
- ON
- ON(0)
- PG5
- ON
- UART0 Message
- OFF(1)
- OFF
- PG9
- PG8
- If botting from QSPI
- ON(0)
- ON(0)
- SPI-NAND, 1-bit
- ON(0)
- OFF(1)
- OFF(1)
- SPI-NAND, 4-bit
- OFF(1)
- OFF(1)
- OFF(1)
- ON(0)
- SPI-NOR, 1-bit
- SPI-NOR, 4-bit
- LED1
- LED2
- LED3
- PG9
- PG8
- If votting from SD/eMMC
- OFF(1)
- OFF(1)
- SD0/eMMC0_PC booting
- Others
- SD1/eMMC1_PF booting
- VD33
- TRST
- TDI
- TMS
- TCK
- TDO
- RES
- TX0
- RX0
- VSS
- RESET
sheet 11
- USB0 HOST
- USB0 Device/HOST
- USB1 HOST
sheet 13
- 1
- VCOM
sheet 14
- EBI
- A0
- A1
- A2
- A3
- D0
- D1
- D2
- D3
- D4
- D5
- D6
- D7
- D10
- D8
- D11
- D9
- D12
- D13
- D14
- D15
- CS1
- WE
- RE
- VD33
- VIN
- VD33
- VIN
- VSS
- VSS
- Expand
- AVSS
- PD8
- PB0
- PD9
- PB1
- PD10
- PB2
- PD11
- PB3
- PG6
- AVD33
- PG7
- PB8
- PC0
- PG8
- PG9
- PE10
- PE12
- VD33
- VD33
- VSS
- VSS
